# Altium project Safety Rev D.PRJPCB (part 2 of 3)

## Sheet SB_PG6.SCHDOC: (Title)
size B; PageSetup: Record=PageOptions|CenterHorizontal=True|CenterVertical=True|PrintScale=1.09|XCorrection=1.00|YCorrection=1.00|PrintKind=0|BorderSize=5000000|LeftOffset=0|BottomOffset=0|Orientation=2|PaperLength=1000|PaperWidth=1000|Scale=100|PaperSource=7|PrintQuality=-4|MediaType=1|DitherType=10|PaperKind=11x17|PrintScaleMode=1; Engineer: (Engineer); Organization: Institute for Astronomy; Address1: 640 N. Aohoku Place; Address2: Hilo, HI 96720; DocumentNumber: T3-2070; Revision: D; SheetNumber: 6; SheetTotal: 16
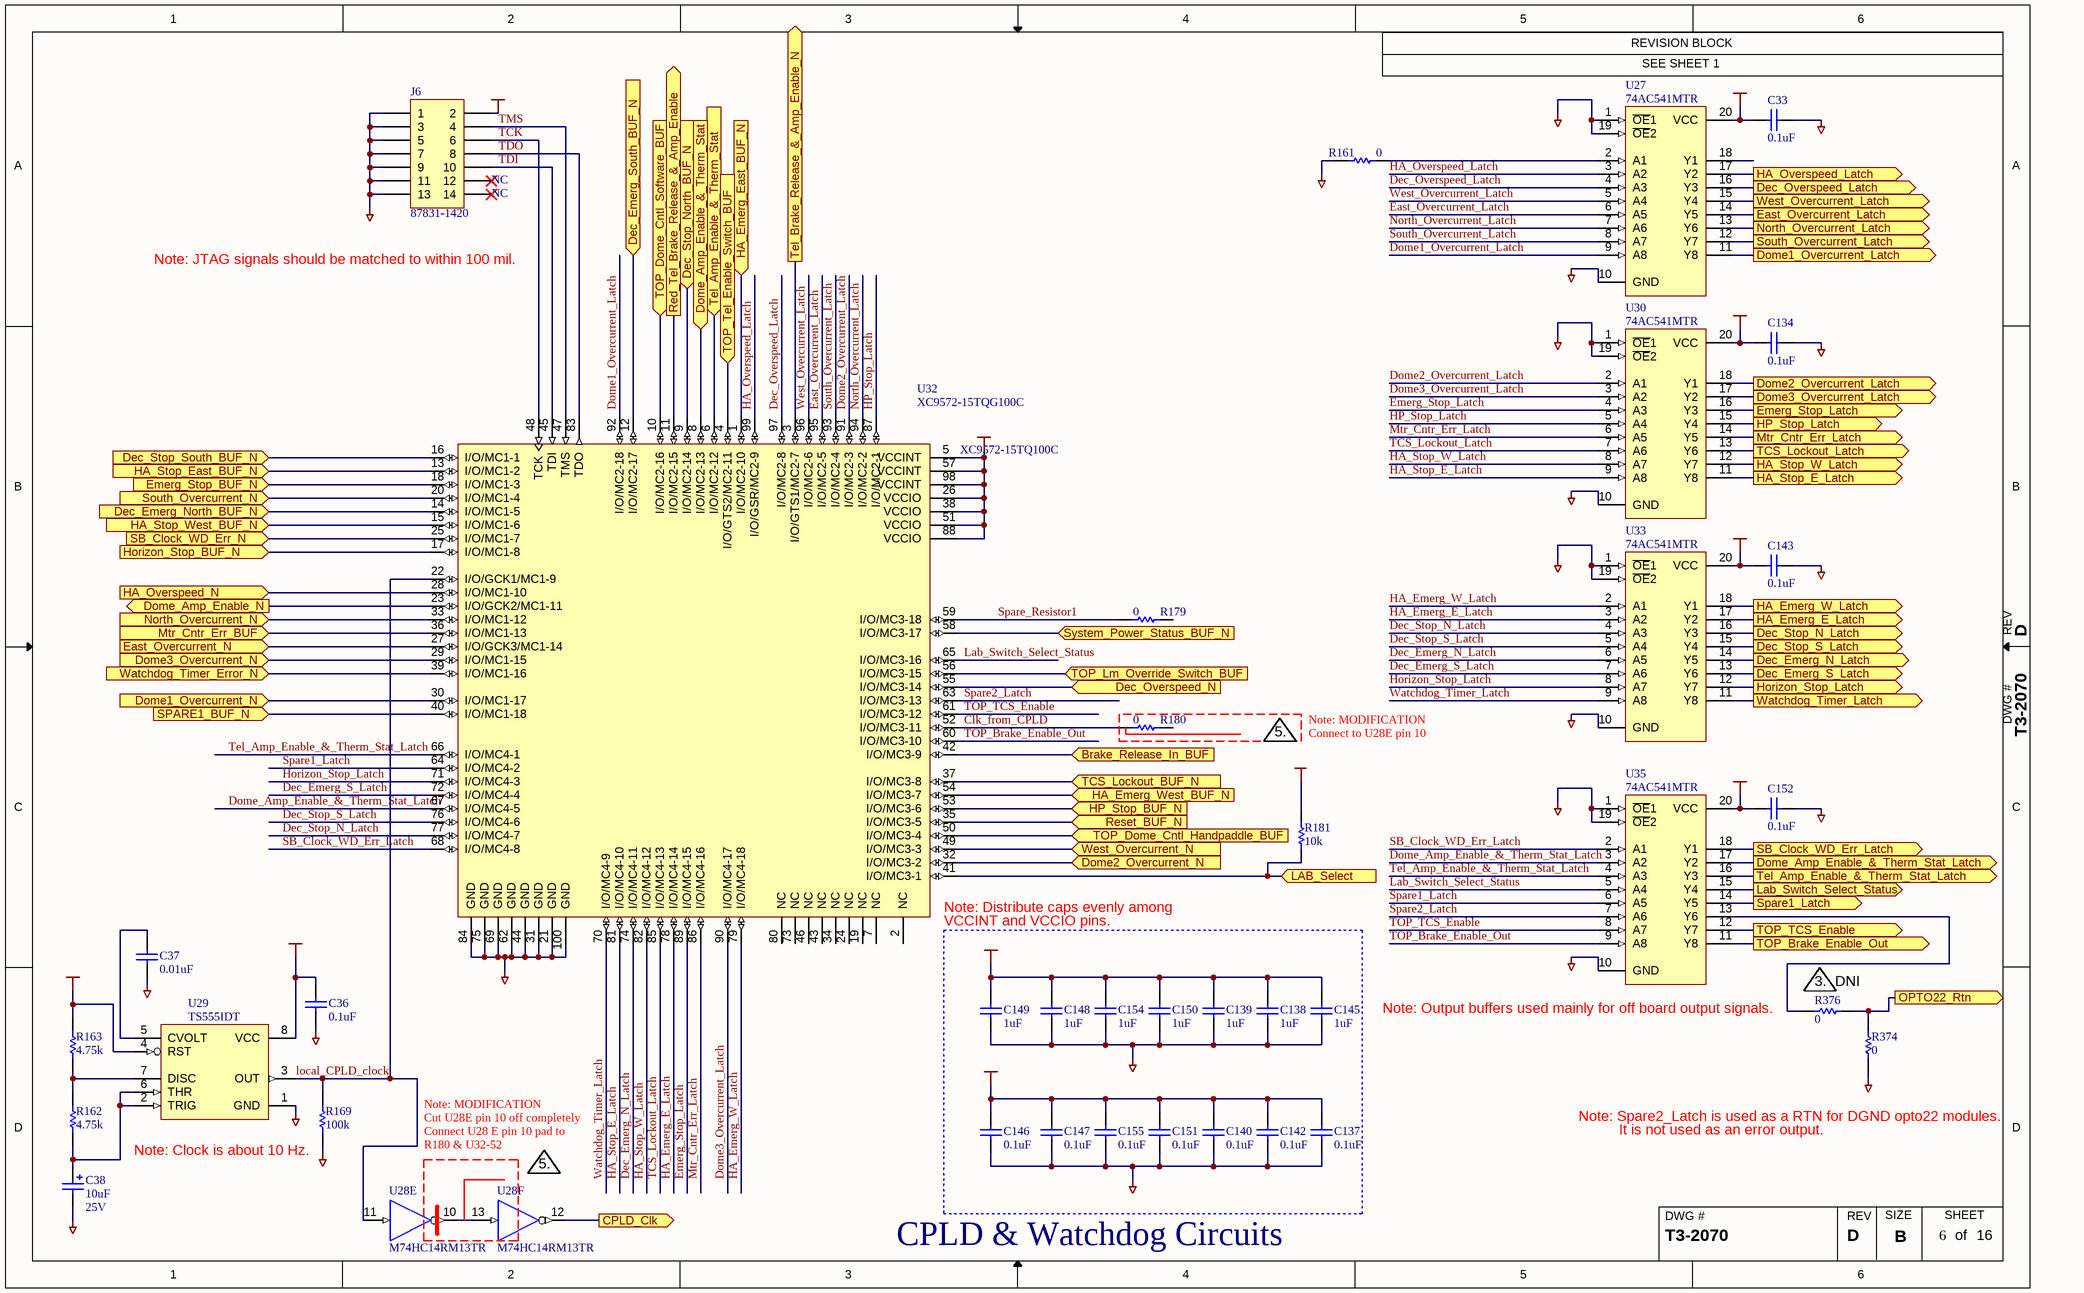
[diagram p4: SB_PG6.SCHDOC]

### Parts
(Parts that share a designator on the sheet are numbered #1, #2 ... from top to bottom, then left to right.)
C33  0.1uF  [1206]
C36  0.1uF  [1206]
C37  0.01uF  [1206]
C38  value 10uF  Voltage: 25V  [CAP_EIA_6032]  (hidden comment: 10uF_25V)
C134  0.1uF  [1206]
C137  0.1uF  [1206]
C138  1uF  [1206]
C139  1uF  [1206]
C140  0.1uF  [1206]
C142  0.1uF  [1206]
C143  0.1uF  [1206]
C145  1uF  [1206]
C146  0.1uF  [1206]
C147  0.1uF  [1206]
C148  1uF  [1206]
C149  1uF  [1206]
C150  1uF  [1206]
C151  0.1uF  [1206]
C152  0.1uF  [1206]
C154  1uF  [1206]
C155  0.1uF  [1206]
Flag?#15  Flag#: 3.  Note: DNI  (graphical)
J6  Part Number: 87831-1420  [HDR_87831-1420]  (hidden comment: Header_14_(7X2)_STR_SHD_col2)
Note?#7  Note#: 5.  (hidden comment: Note_Flag)  (graphical)
Note?#8  Note#: 5.  (hidden comment: Note_Flag)  (graphical)
R161  value 0  [1206]  (hidden comment: 0_jumper)
R162  value 4.75k  [1206]  (hidden comment: 4750)
R163  value 4.75k  [1206]  (hidden comment: 4750)
R169  value 100k  [1206]  (hidden comment: 100000)
R179  value 0  [1206]  (hidden comment: 0_jumper)
R180  value 0  [1206]  (hidden comment: 0_jumper)
R181  value 10k  [1206]  (hidden comment: 10000)
R374  value 0  [1206]  (hidden comment: 0_jumper)
R376  value 0  [1206]  (hidden comment: 0_jumper)  (no BOM)
U27  Part Number: 74AC541MTR  [SOIC_20_WIDE]  (hidden comment: M74HCT541M1R)
U28  M74HC14RM13TR  [SOIC_14_Narrow]  (parts E,F of 6)
U29  TS555IDT  [SOIC_8_NARROW]
U30  Part Number: 74AC541MTR  [SOIC_20_WIDE]  (hidden comment: M74HCT541M1R)
U32  XC9572-15TQ100C  Part Number: XC9572-15TQG100C  [TQ100]
U33  Part Number: 74AC541MTR  [SOIC_20_WIDE]  (hidden comment: M74HCT541M1R)
U35  Part Number: 74AC541MTR  [SOIC_20_WIDE]  (hidden comment: M74HCT541M1R)

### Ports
Brake_Release_In_BUF (in), CPLD_Clk (out), Dec_Emerg_N_Latch (out), Dec_Emerg_North_BUF_N (in), Dec_Emerg_S_Latch (out), Dec_Emerg_South_BUF_N (in), Dec_Overspeed_Latch (out), Dec_Overspeed_N (in), Dec_Stop_N_Latch (out), Dec_Stop_North_BUF_N (in), Dec_Stop_S_Latch (out), Dec_Stop_South_BUF_N (in), Dome1_Overcurrent_Latch (out), Dome1_Overcurrent_N (in), Dome2_Overcurrent_Latch (out), Dome2_Overcurrent_N (in), Dome3_Overcurrent_Latch (out), Dome3_Overcurrent_N (in), Dome_Amp_Enable_&_Therm_Stat (in), Dome_Amp_Enable_&_Therm_Stat_Latch (out), Dome_Amp_Enable_N (out), East_Overcurrent_Latch (out), East_Overcurrent_N (in), Emerg_Stop_BUF_N (in), Emerg_Stop_Latch (out), HA_Emerg_E_Latch (out), HA_Emerg_East_BUF_N (in), HA_Emerg_W_Latch (out), HA_Emerg_West_BUF_N (in), HA_Overspeed_Latch (out), HA_Overspeed_N (in), HA_Stop_E_Latch (out), HA_Stop_East_BUF_N (in), HA_Stop_W_Latch (out), HA_Stop_West_BUF_N (in), Horizon_Stop_BUF_N (in), Horizon_Stop_Latch (out), HP_Stop_BUF_N (in), HP_Stop_Latch (out), LAB_Select (in), Lab_Switch_Select_Status (out), Mtr_Cntr_Err_BUF (in), Mtr_Cntr_Err_Latch (out), North_Overcurrent_Latch (out), North_Overcurrent_N (in), OPTO22_Rtn (out), Red_Tel_Brake_Release_&_Amp_Enable (out), Reset_BUF_N (in), SB_Clock_WD_Err_Latch (out), SB_Clock_WD_Err_N (in), South_Overcurrent_Latch (out), South_Overcurrent_N (in), SPARE1_BUF_N (in), Spare1_Latch (out), System_Power_Status_BUF_N (in), TCS_Lockout_BUF_N (in), TCS_Lockout_Latch (out), Tel_Amp_Enable_&_Therm_Stat (in), Tel_Amp_Enable_&_Therm_Stat_Latch (out), Tel_Brake_Release_&_Amp_Enable_N (out), TOP_Brake_Enable_Out (out), TOP_Dome_Cntl_Handpaddle_BUF (in), TOP_Dome_Cntl_Software_BUF (in), TOP_Lm_Override_Switch_BUF (in), TOP_TCS_Enable (out), TOP_Tel_Enable_Switch_BUF (in), Watchdog_Timer_Error_N (in), Watchdog_Timer_Latch (out), West_Overcurrent_Latch (out), West_Overcurrent_N (in)

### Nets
+5V_DIG: C33.2 C36.2 C134.2 C137.2 C138.2 C139.2 C140.2 C142.2 C143.2 C145.2 C146.2 C147.2 C148.2 C149.2 C150.2 C151.2 C152.2 C154.2 C155.2 J6.2 R163.2 R181.2 U27.20(VCC) U29.4(RST) U29.8(VCC) U30.20(VCC) U32.5(VCCINT) U32.26(VCCIO) U32.38(VCCIO) U32.51(VCCIO) U32.57(VCCINT) U32.88(VCCIO) U32.98(VCCINT) U33.20(VCC) U35.20(VCC)
DGND: C33.1 C36.1 C37.1 C38.2 C134.1 C137.1 C138.1 C139.1 C140.1 C142.1 C143.1 C145.1 C146.1 C147.1 C148.1 C149.1 C150.1 C151.1 C152.1 C154.1 C155.1 J6.1 J6.3 J6.5 J6.7 J6.9 J6.11 J6.13 R161.1 R169.1 R374.1 U27.1(~{OE}1) U27.10(GND) U27.19(~{OE}2) U29.1(GND) U30.1(~{OE}1) U30.10(GND) U30.19(~{OE}2) U32.21(GND) U32.31(GND) U32.44(GND) U32.62(GND) U32.69(GND) U32.75(GND) U32.84(GND) U32.100(GND) U33.1(~{OE}1) U33.10(GND) U33.19(~{OE}2) U35.1(~{OE}1) U35.10(GND) U35.19(~{OE}2)
Brake_Release_In_BUF: U32.42(I/O/MC3-9) ; port Brake_Release_In_BUF
Clk_from_CPLD: R180.1 U32.52(I/O/MC3-11)
CPLD_Clk: U28.12(~{OUT}) ; port CPLD_Clk
Dec Emerg N Latch: U33.14(Y5) ; port Dec_Emerg_N_Latch
Dec Emerg S Latch: U33.13(Y6) ; port Dec_Emerg_S_Latch
Dec OS Latch: U27.16(Y3) ; port Dec_Overspeed_Latch
Dec Stop N Latch: U33.16(Y3) ; port Dec_Stop_N_Latch
Dec Stop S Latch: U33.15(Y4) ; port Dec_Stop_S_Latch
Dec_Emerg_N_Latch: U32.74(I/O/MC4-11) U33.6(A5)
Dec_Emerg_North_BUF_N: U32.14(I/O/MC1-5) ; port Dec_Emerg_North_BUF_N
Dec_Emerg_S_Latch: U32.72(I/O/MC4-4) U33.7(A6)
Dec_Emerg_South_BUF_N: U32.12(I/O/MC2-17) ; port Dec_Emerg_South_BUF_N
Dec_Lab_Select: R181.1 U32.41(I/O/MC3-1) ; port LAB_Select
Dec_Overspeed_Latch: U27.4(A3) U32.97(I/O/MC2-8)
Dec_Overspeed_N: U32.55(I/O/MC3-14) ; port Dec_Overspeed_N
Dec_Stop_N_Latch: U32.77(I/O/MC4-7) U33.4(A3)
Dec_Stop_North_BUF_N: U32.9(I/O/MC2-14) ; port Dec_Stop_North_BUF_N
Dec_Stop_S_Latch: U32.76(I/O/MC4-6) U33.5(A4)
Dec_Stop_South_BUF_N: U32.16(I/O/MC1-1) ; port Dec_Stop_South_BUF_N
Dome1 OC Latch: U27.11(Y8) ; port Dome1_Overcurrent_Latch
Dome1_Overcurrent_Latch: U27.9(A8) U32.92(I/O/MC2-18)
Dome1_Overcurrent_N: U32.30(I/O/MC1-17) ; port Dome1_Overcurrent_N
Dome2 OC Latch: U30.18(Y1) ; port Dome2_Overcurrent_Latch
Dome2_Overcurrent_Latch: U30.2(A1) U32.91(I/O/MC2-3)
Dome2_Overcurrent_N: U32.32(I/O/MC3-2) ; port Dome2_Overcurrent_N
Dome3 OC Latch: U30.17(Y2) ; port Dome3_Overcurrent_Latch
Dome3_Overcurrent_Latch: U30.3(A2) U32.90(I/O/MC4-17)
Dome3_Overcurrent_N: U32.29(I/O/MC1-15) ; port Dome3_Overcurrent_N
Dome Amp Enable & Therm Stat Latch: U35.17(Y2) ; port Dome_Amp_Enable_&_Therm_Stat_Latch
Dome_Amp_Enable_&_Therm_Stat: U32.8(I/O/MC2-13) ; port Dome_Amp_Enable_&_Therm_Stat
Dome_Amp_Enable_&_Therm_Stat_Latch: U32.67(I/O/MC4-5) U35.3(A2)
Dome_Amp_Enable_N: U32.23(I/O/GCK2/MC1-11) ; port Dome_Amp_Enable_N
East OC Latch: U27.14(Y5) ; port East_Overcurrent_Latch
East_Overcurrent_Latch: U27.6(A5) U32.95(I/O/MC2-5)
East_Overcurrent_N: U32.27(I/O/GCK3/MC1-14) ; port East_Overcurrent_N
Emerg Stop Latch: U30.16(Y3) ; port Emerg_Stop_Latch
Emerg_Stop_BUF_N: U32.18(I/O/MC1-3) ; port Emerg_Stop_BUF_N
Emerg_Stop_Latch: U30.4(A3) U32.89(I/O/MC4-15)
HA Emerg E Latch: U33.17(Y2) ; port HA_Emerg_E_Latch
HA Emerg W Latch: U33.18(Y1) ; port HA_Emerg_W_Latch
HA OS Latch: U27.17(Y2) ; port HA_Overspeed_Latch
HA Stop E Latch: U30.11(Y8) ; port HA_Stop_E_Latch
HA Stop W Latch: U30.12(Y7) ; port HA_Stop_W_Latch
HA_Emerg_E_Latch: U32.78(I/O/MC4-14) U33.3(A2)
HA_Emerg_East_BUF_N: U32.1(I/O/MC2-10) ; port HA_Emerg_East_BUF_N
HA_Emerg_W_Latch: U32.79(I/O/MC4-18) U33.2(A1)
HA_Emerg_West_BUF_N: U32.54(I/O/MC3-7) ; port HA_Emerg_West_BUF_N
HA_Overspeed_Latch: U27.3(A2) U32.99(I/O/GSR/MC2-9)
HA_Overspeed_N: U32.28(I/O/MC1-10) ; port HA_Overspeed_N
HA_Stop_E_Latch: U30.9(A8) U32.81(I/O/MC4-10)
HA_Stop_East_BUF_N: U32.13(I/O/MC1-2) ; port HA_Stop_East_BUF_N
HA_Stop_W_Latch: U30.8(A7) U32.82(I/O/MC4-12)
HA_Stop_West_BUF_N: U32.15(I/O/MC1-6) ; port HA_Stop_West_BUF_N
Horizon Stop Latch: U33.12(Y7) ; port Horizon_Stop_Latch
Horizon_Stop_BUF_N: U32.17(I/O/MC1-8) ; port Horizon_Stop_BUF_N
Horizon_Stop_Latch: U32.71(I/O/MC4-3) U33.8(A7)
HP Stop Latch: U30.15(Y4) ; port HP_Stop_Latch
HP_Stop_BUF_N: U32.53(I/O/MC3-6) ; port HP_Stop_BUF_N
HP_Stop_Latch: U30.5(A4) U32.87(I/O/MC2-1)
Lab Switch Select Status: U35.15(Y4) ; port Lab_Switch_Select_Status
Lab_Switch_Select_Status: U32.65(I/O/MC3-16) U35.5(A4)
local_CPLD_clock: R169.2 U28.11(IN) U29.3(OUT) U32.22(I/O/GCK1/MC1-9)
Mtr Cntr Err Latch: U30.14(Y5) ; port Mtr_Cntr_Err_Latch
Mtr_Cntr_Err_BUF: U32.36(I/O/MC1-13) ; port Mtr_Cntr_Err_BUF
Mtr_Cntr_Err_Latch: U30.6(A5) U32.86(I/O/MC4-16)
North OC Latch: U27.13(Y6) ; port North_Overcurrent_Latch
North_Overcurrent_Latch: U27.7(A6) U32.94(I/O/MC2-2)
North_Overcurrent_N: U32.33(I/O/MC1-12) ; port North_Overcurrent_N
Red_Tel_Brake_Release_&_Amp_Enable: U32.11(I/O/MC2-15) ; port Red_Tel_Brake_Release_&_Amp_Enable
Reset_BUF_N: U32.35(I/O/MC3-5) ; port Reset_BUF_N
SB OPTO22 Rtn: R374.2 R376.2 ; port OPTO22_Rtn
SB_Clock_WD_Err_Latch: U35.18(Y1) ; port SB_Clock_WD_Err_Latch
SB_Clock_WD_Err_Latch: U32.68(I/O/MC4-8) U35.2(A1)  [a separate net that carries the same name]
SB_Clock_WD_Err_N: U32.25(I/O/MC1-7) ; port SB_Clock_WD_Err_N
South OS Latch: U27.12(Y7) ; port South_Overcurrent_Latch
South_Overcurrent_Latch: U27.8(A7) U32.93(I/O/MC2-4)
South_Overcurrent_N: U32.20(I/O/MC1-4) ; port South_Overcurrent_N
SPARE1_BUF_N: U32.40(I/O/MC1-18) ; port SPARE1_BUF_N
Spare1_Latch: U32.64(I/O/MC4-2) U35.6(A5)
Spare2_Latch: U32.63(I/O/MC3-13) U35.7(A6)
Spare Latch Out 1: U35.14(Y5) ; port Spare1_Latch
Spare_Resistor1: R179.1 U32.59(I/O/MC3-18)
System_Power_Status_BUF_N: U32.58(I/O/MC3-17) ; port System_Power_Status_BUF_N
TCK: J6.6 U32.48(TCK)
TCS Lockout Latch: U30.13(Y6) ; port TCS_Lockout_Latch
TCS_Lockout_BUF_N: U32.37(I/O/MC3-8) ; port TCS_Lockout_BUF_N
TCS_Lockout_Latch: U30.7(A6) U32.85(I/O/MC4-13)
TDI: J6.10 U32.45(TDI)
TDO: J6.8 U32.83(TDO)
Tel Amp Enable & Therm Stat Latch: U35.16(Y3) ; port Tel_Amp_Enable_&_Therm_Stat_Latch
Tel_Amp_Enable_&_Therm_Stat: U32.6(I/O/MC2-12) ; port Tel_Amp_Enable_&_Therm_Stat
Tel_Amp_Enable_&_Therm_Stat_Latch: U32.66(I/O/MC4-1) U35.4(A3)
Tel_Brake_Release_&_Amp_Enable_N: U32.3(I/O/GTS1/MC2-7) ; port Tel_Brake_Release_&_Amp_Enable_N
TMS: J6.4 U32.47(TMS)
TOP Brake Enable Out: U35.11(Y8) ; port TOP_Brake_Enable_Out
TOP TCS Enable: U35.12(Y7) ; port TOP_TCS_Enable
TOP_Brake_Enable_Out: U32.60(I/O/MC3-10) U35.9(A8)
TOP_Dome_Cntl_Handpaddle_BUF: U32.50(I/O/MC3-4) ; port TOP_Dome_Cntl_Handpaddle_BUF
TOP_Dome_Cntl_Software_BUF: U32.10(I/O/MC2-16) ; port TOP_Dome_Cntl_Software_BUF
TOP_Lm_Override_Switch_BUF: U32.56(I/O/MC3-15) ; port TOP_Lm_Override_Switch_BUF
TOP_TCS_Enable: U32.61(I/O/MC3-12) U35.8(A7)
TOP_Tel_Enable_Switch_BUF: U32.4(I/O/GTS2/MC2-11) ; port TOP_Tel_Enable_Switch_BUF
Watchdog Timer Latch: U33.11(Y8) ; port Watchdog_Timer_Latch
Watchdog_Timer_Error_N: U32.39(I/O/MC1-16) ; port Watchdog_Timer_Error_N
Watchdog_Timer_Latch: U32.70(I/O/MC4-9) U33.9(A8)
West OC Latch: U27.15(Y4) ; port West_Overcurrent_Latch
West_Overcurrent_Latch: U27.5(A4) U32.96(I/O/MC2-6)
West_Overcurrent_N: U32.49(I/O/MC3-3) ; port West_Overcurrent_N
NetC37_2: C37.2 U29.5(CVOLT)
NetC38_1: C38.1 R162.1 U29.2(TRIG) U29.6(THR)
NetR161_2: R161.2 U27.2(A1)
NetR162_2: R162.2 R163.1 U29.7(DISC)
NetR376_1: R376.1 U35.13(Y6)
NetU28_10: U28.10(~{OUT}) U28.13(IN)

Not connected (* = marked no-connect by the designer): J6 12* 14*; R179 2; R180 2; U27 18(Y1); U32 2(NC) 7(NC) 19(NC) 24(NC) 34(NC) 43(NC) 46(NC) 73(NC) 80(NC)

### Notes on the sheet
- (near J6) NC
- Note: JTAG signals should be matched to within 100 mil.
- (near Note?#7) Note: MODIFICATION
- (near Note?#7) Connect to U28E pin 10
- (near U32) Note: Distribute caps evenly among
- (near U32) VCCINT and VCCIO pins.
- (near R376) Note: Output buffers used mainly for off board output signals.
- (near Note?#8) Note: MODIFICATION
- (near R169) Note: Clock is about 10 Hz.
- (near Note?#8) Cut U28E pin 10 off completely
- (near Note?#8) Connect U28 E pin 10 pad to
- (near Note?#8) R180 & U32-52
- (near R374) Note: Spare2_Latch is used as a RTN for DGND opto22 modules.
- It is not used as an error output.
- CPLD & Watchdog Circuits

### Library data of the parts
C33 C36 C134 C137 C140 C142 C143 C146 C147 C151 C152 C155 = 0.1uF: Ceramic Chip Capacitor, 0.1uF, 50V, 10%, X7R; Part Number: C1206C104K5RACTU; Manufacturer: Kemet; BOM_IGNORE: False
C37 = 0.01uF: Ceramic Chip Capacitor, 0.01uF, 50V, 10%, X7R; Part Number: C1206C103K5RACTU; Manufacturer: Kemet; BOM_IGNORE: False
C38 = 10uF_25V: CAP TANTALUM, 10UF, 25V, 10%; Part Number: TAJC106K025R; Manufacturer: AVX
C138 C139 C145 C148-C150 C154 = 1uF: Ceramic Chip Capacitor, 1uF, 50V, 10%, X7R; Part Number: C1206F105K5RACTU; Manufacturer: Kemet; BOM_IGNORE: False
Flag?#15 = Flag
J6 = Header_14_(7X2)_STR_SHD_col2: Header, 14-Pin, Dual row, Straight, Shroud; Manufacturer: Molex/Waldom Electronics Corp.
Note?#7 Note?#8 = Note_Flag: Flag Note; Line1: Physical Modifications:; Line2: Wires, cuts, jumps, etc.; Line3: (line 3)
R161 R179 R180 R374 R376 = 0_jumper: Thick Film Chip Resistor, 0 Ohm, 1206 Size, 0.25 W; Part Number: ERJ-8GEY0R00V; Manufacturer: Panasonic; Tolerance: 1%; Power Rating: 0.25W
R162 R163 = 4750: Thick Film Chip Resistor, 4.75k Ohm, 1% Tolerance, 1206 Size, 0.25 W; Part Number: ERJ-8ENF4751V; Manufacturer: Panasonic; Power Rating: 0.25W
R169 = 100000: Thick Film Chip Resistor, 100k Ohm, 1% Tolerance, 1206 Size, 0.25 W; Part Number: ERJ-8ENF1003V; Manufacturer: Panasonic; Power Rating: 0.25W
R181 = 10000: Thick Film Chip Resistor, 10k Ohm, 1% Tolerance, 1206 Size, 0.25 W; Part Number: ERJ-8ENF1002V; Manufacturer: Panasonic; Power Rating: 0.25W
U27 U30 U33 U35 = M74HCT541M1R: Octal Bus Buffer with 3 State Outputs (Non Inverted); Manufacturer: STMicroelectronics
U28 = M74HC14RM13TR: Hex Schmitt-Trigger Inverter; Manufacturer: STMicroelectronics
U29 = TS555IDT: IC PRECISION TIMER , CMOS, 8-SOIC; Manufacturer: STMicroelectronics
U32 = XC9572-15TQ100C: XC9500 CPLD with 72 Macrocells, 100-Pin TQFP, Commercial Grade; Manufacturer: Xilinx

## Sheet SB_PG3.SCHDOC: (Title)
size B; PageSetup: Record=PageOptions|CenterHorizontal=True|CenterVertical=True|PrintScale=1.09|XCorrection=1.00|YCorrection=1.00|PrintKind=0|BorderSize=5000000|LeftOffset=0|BottomOffset=0|Orientation=2|PaperLength=1000|PaperWidth=1000|Scale=100|PaperSource=7|PrintQuality=-4|MediaType=1|DitherType=10|PaperKind=11x17|PrintScaleMode=1; Engineer: (Engineer); Organization: Institute for Astronomy; Address1: 640 N. Aohoku Place; Address2: Hilo, HI 96720; DocumentNumber: T3-2070; Revision: D; SheetNumber: 3; SheetTotal: 16
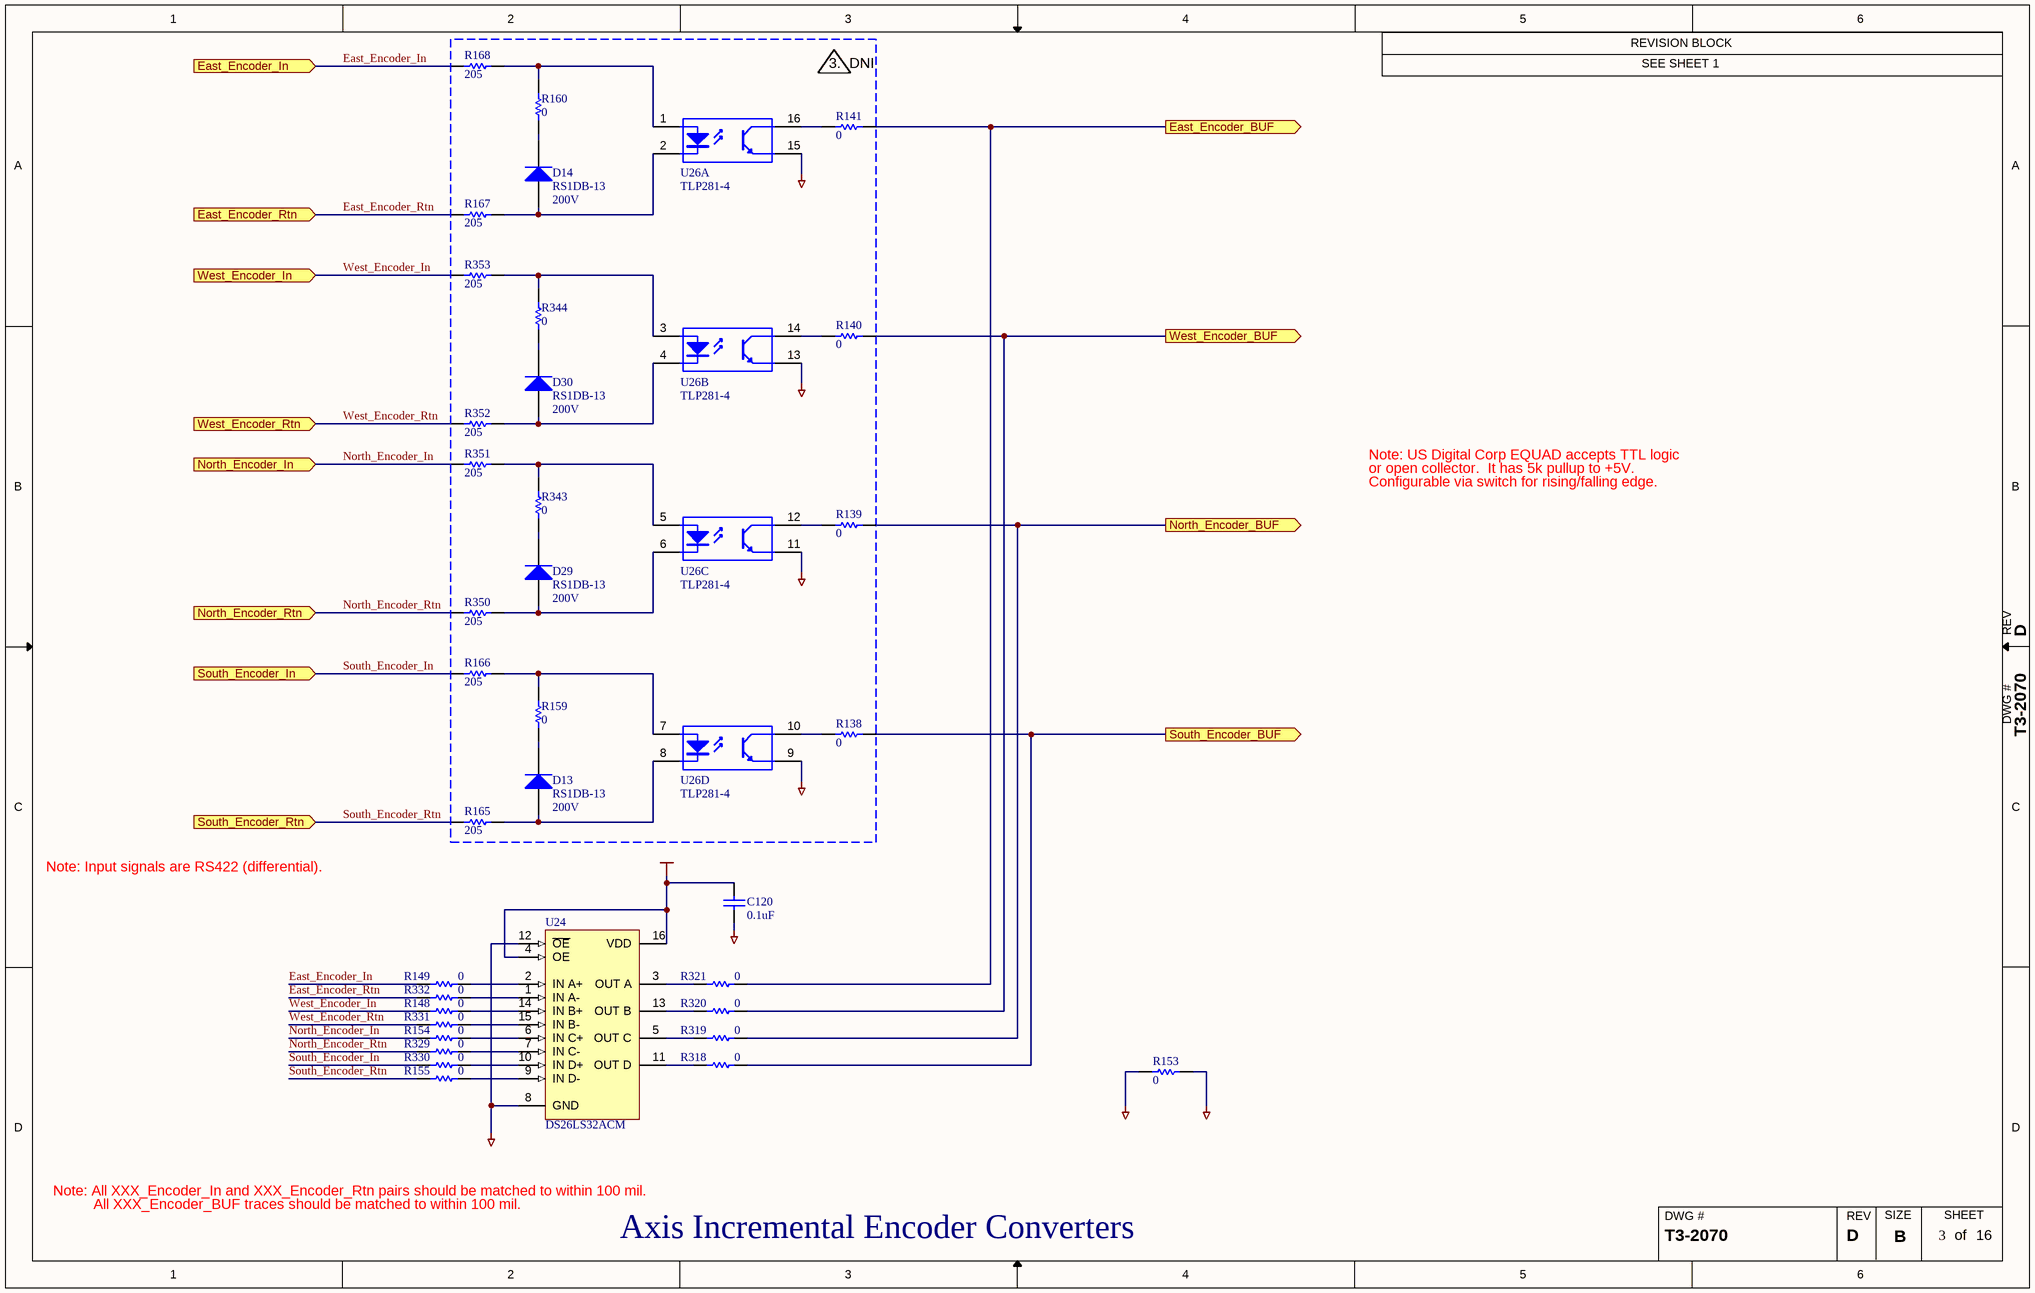
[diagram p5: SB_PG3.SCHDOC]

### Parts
(Parts that share a designator on the sheet are numbered #1, #2 ... from top to bottom, then left to right.)
C120  0.1uF  [1206]
D13  Voltage: 200V  [DO-214AA (SMB) & MARKING]  (hidden comment: RS1DB-13)  (no BOM)
D14  Voltage: 200V  [DO-214AA (SMB) & MARKING]  (hidden comment: RS1DB-13)  (no BOM)
D29  Voltage: 200V  [DO-214AA (SMB) & MARKING]  (hidden comment: RS1DB-13)  (no BOM)
D30  Voltage: 200V  [DO-214AA (SMB) & MARKING]  (hidden comment: RS1DB-13)  (no BOM)
Flag?#16  Flag#: 3.  Note: DNI  (graphical)
R138  value 0  [1206]  (hidden comment: 0_jumper)  (no BOM)
R139  value 0  [1206]  (hidden comment: 0_jumper)  (no BOM)
R140  value 0  [1206]  (hidden comment: 0_jumper)  (no BOM)
R141  value 0  [1206]  (hidden comment: 0_jumper)  (no BOM)
R148  value 0  [1206]  (hidden comment: 0_jumper)
R149  value 0  [1206]  (hidden comment: 0_jumper)
R153  value 0  [1206]  (hidden comment: 0_jumper)
R154  value 0  [1206]  (hidden comment: 0_jumper)
R155  value 0  [1206]  (hidden comment: 0_jumper)
R159  value 0  [1206]  (hidden comment: 0_jumper)  (no BOM)
R160  value 0  [1206]  (hidden comment: 0_jumper)  (no BOM)
R165  205  [1206]  (no BOM)
R166  205  [1206]  (no BOM)
R167  205  [1206]  (no BOM)
R168  205  [1206]  (no BOM)
R318  value 0  [1206]  (hidden comment: 0_jumper)
R319  value 0  [1206]  (hidden comment: 0_jumper)
R320  value 0  [1206]  (hidden comment: 0_jumper)
R321  value 0  [1206]  (hidden comment: 0_jumper)
R329  value 0  [1206]  (hidden comment: 0_jumper)
R330  value 0  [1206]  (hidden comment: 0_jumper)
R331  value 0  [1206]  (hidden comment: 0_jumper)
R332  value 0  [1206]  (hidden comment: 0_jumper)
R343  value 0  [1206]  (hidden comment: 0_jumper)  (no BOM)
R344  value 0  [1206]  (hidden comment: 0_jumper)  (no BOM)
R350  205  [1206]  (no BOM)
R351  205  [1206]  (no BOM)
R352  205  [1206]  (no BOM)
R353  205  [1206]  (no BOM)
U24  DS26LS32ACM  [SOIC_16_NARROW]
U26  TLP281-4  [SOIC_16_C5.85]  (parts A,B,C,D of 4)  (no BOM)

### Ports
East_Encoder_BUF (out), East_Encoder_In (in), East_Encoder_Rtn (in), North_Encoder_BUF (out), North_Encoder_In (in), North_Encoder_Rtn (in), South_Encoder_BUF (out), South_Encoder_In (in), South_Encoder_Rtn (in), West_Encoder_BUF (out), West_Encoder_In (in), West_Encoder_Rtn (in)

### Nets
+5V_DIG: C120.2 U24.4(OE) U24.16(VDD)
DGND: C120.1 R153.1 U24.8(GND) U24.12(~{OE}) U26.9(E) U26.11(E) U26.13(E) U26.15(E)
EGND: R153.2
East_Encoder_BUF: R141.1 R321.2 ; port East_Encoder_BUF
East_Encoder_In: R149.1 R168.1 ; port East_Encoder_In
East_Encoder_Rtn: R167.1 R332.1 ; port East_Encoder_Rtn
North_Encoder_BUF: R139.1 R319.2 ; port North_Encoder_BUF
North_Encoder_In: R154.1 R351.1 ; port North_Encoder_In
North_Encoder_Rtn: R329.1 R350.1 ; port North_Encoder_Rtn
South_Encoder_BUF: R138.1 R318.2 ; port South_Encoder_BUF
South_Encoder_In: R166.1 R330.1 ; port South_Encoder_In
South_Encoder_Rtn: R155.1 R165.1 ; port South_Encoder_Rtn
West_Encoder_BUF: R140.1 R320.2 ; port West_Encoder_BUF
West_Encoder_In: R148.1 R353.1 ; port West_Encoder_In
West_Encoder_Rtn: R331.1 R352.1 ; port West_Encoder_Rtn
NetD13_A: D13.A R165.2 U26.8(K)
NetD13_K: D13.K R159.1
NetD14_A: D14.A R167.2 U26.2(K)
NetD14_K: D14.K R160.1
NetD29_A: D29.A R350.2 U26.6(K)
NetD29_K: D29.K R343.1
NetD30_A: D30.A R352.2 U26.4(K)
NetD30_K: D30.K R344.1
NetR138_2: R138.2 U26.10(C)
NetR139_2: R139.2 U26.12(C)
NetR140_2: R140.2 U26.14(C)
NetR141_2: R141.2 U26.16(C)
NetR148_2: R148.2 U24.14(IN_B+)
NetR149_2: R149.2 U24.2(IN_A+)
NetR154_2: R154.2 U24.6(IN_C+)
NetR155_2: R155.2 U24.9(IN_D-)
NetR159_2: R159.2 R166.2 U26.7(A)
NetR160_2: R160.2 R168.2 U26.1(A)
NetR318_1: R318.1 U24.11(OUT_D)
NetR319_1: R319.1 U24.5(OUT_C)
NetR320_1: R320.1 U24.13(OUT_B)
NetR321_1: R321.1 U24.3(OUT_A)
NetR329_2: R329.2 U24.7(IN_C-)
NetR330_2: R330.2 U24.10(IN_D+)
NetR331_2: R331.2 U24.15(IN_B-)
NetR332_2: R332.2 U24.1(IN_A-)
NetR343_2: R343.2 R351.2 U26.5(A)
NetR344_2: R344.2 R353.2 U26.3(A)

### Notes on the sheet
- Note: US Digital Corp EQUAD accepts TTL logic
- or open collector.  It has 5k pullup to +5V.
- Configurable via switch for rising/falling edge.
- Note: Input signals are RS422 (differential).
- Note: All XXX_Encoder_In and XXX_Encoder_Rtn pairs should be matched to within 100 mil.
- All XXX_Encoder_BUF traces should be matched to within 100 mil.
- Axis Incremental Encoder Converters

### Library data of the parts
C120 = 0.1uF: as C33 on sheet SB_PG6
D13 D14 D29 D30 = RS1DB-13: RECT FAST RECOVERY 200V 1A; Manufacturer: Diodes Inc
Flag?#16 = Flag
R138-R141 R148 R149 R153-R155 R159 R160 R318-R321 R329-R332 R343 R344 = 0_jumper: as R161 on sheet SB_PG6
R165-R168 R350-R353 = 205: Thick Film Chip Resistor, 205 Ohm, 1% Tolerance, 1206 Size, 0.25 W; Part Number: ERJ-8ENF2050V; Manufacturer: Panasonic; Power Rating: 0.25W; BOM_IGNORE: False
U24 = DS26LS32ACM: IC LINE RCVR QUAD DIFF; Manufacturer: National Semiconductor
U26 = TLP281-4: Photocoupler; Manufacturer: Toshiba

## Sheet SB_PG2.SCHDOC: (Title)
size B; Engineer: (Engineer); Organization: Institute for Astronomy; Address1: 640 N. Aohoku Place; Address2: Hilo, HI 96720; DocumentNumber: T3-2070; Revision: D; SheetNumber: 2; SheetTotal: 16
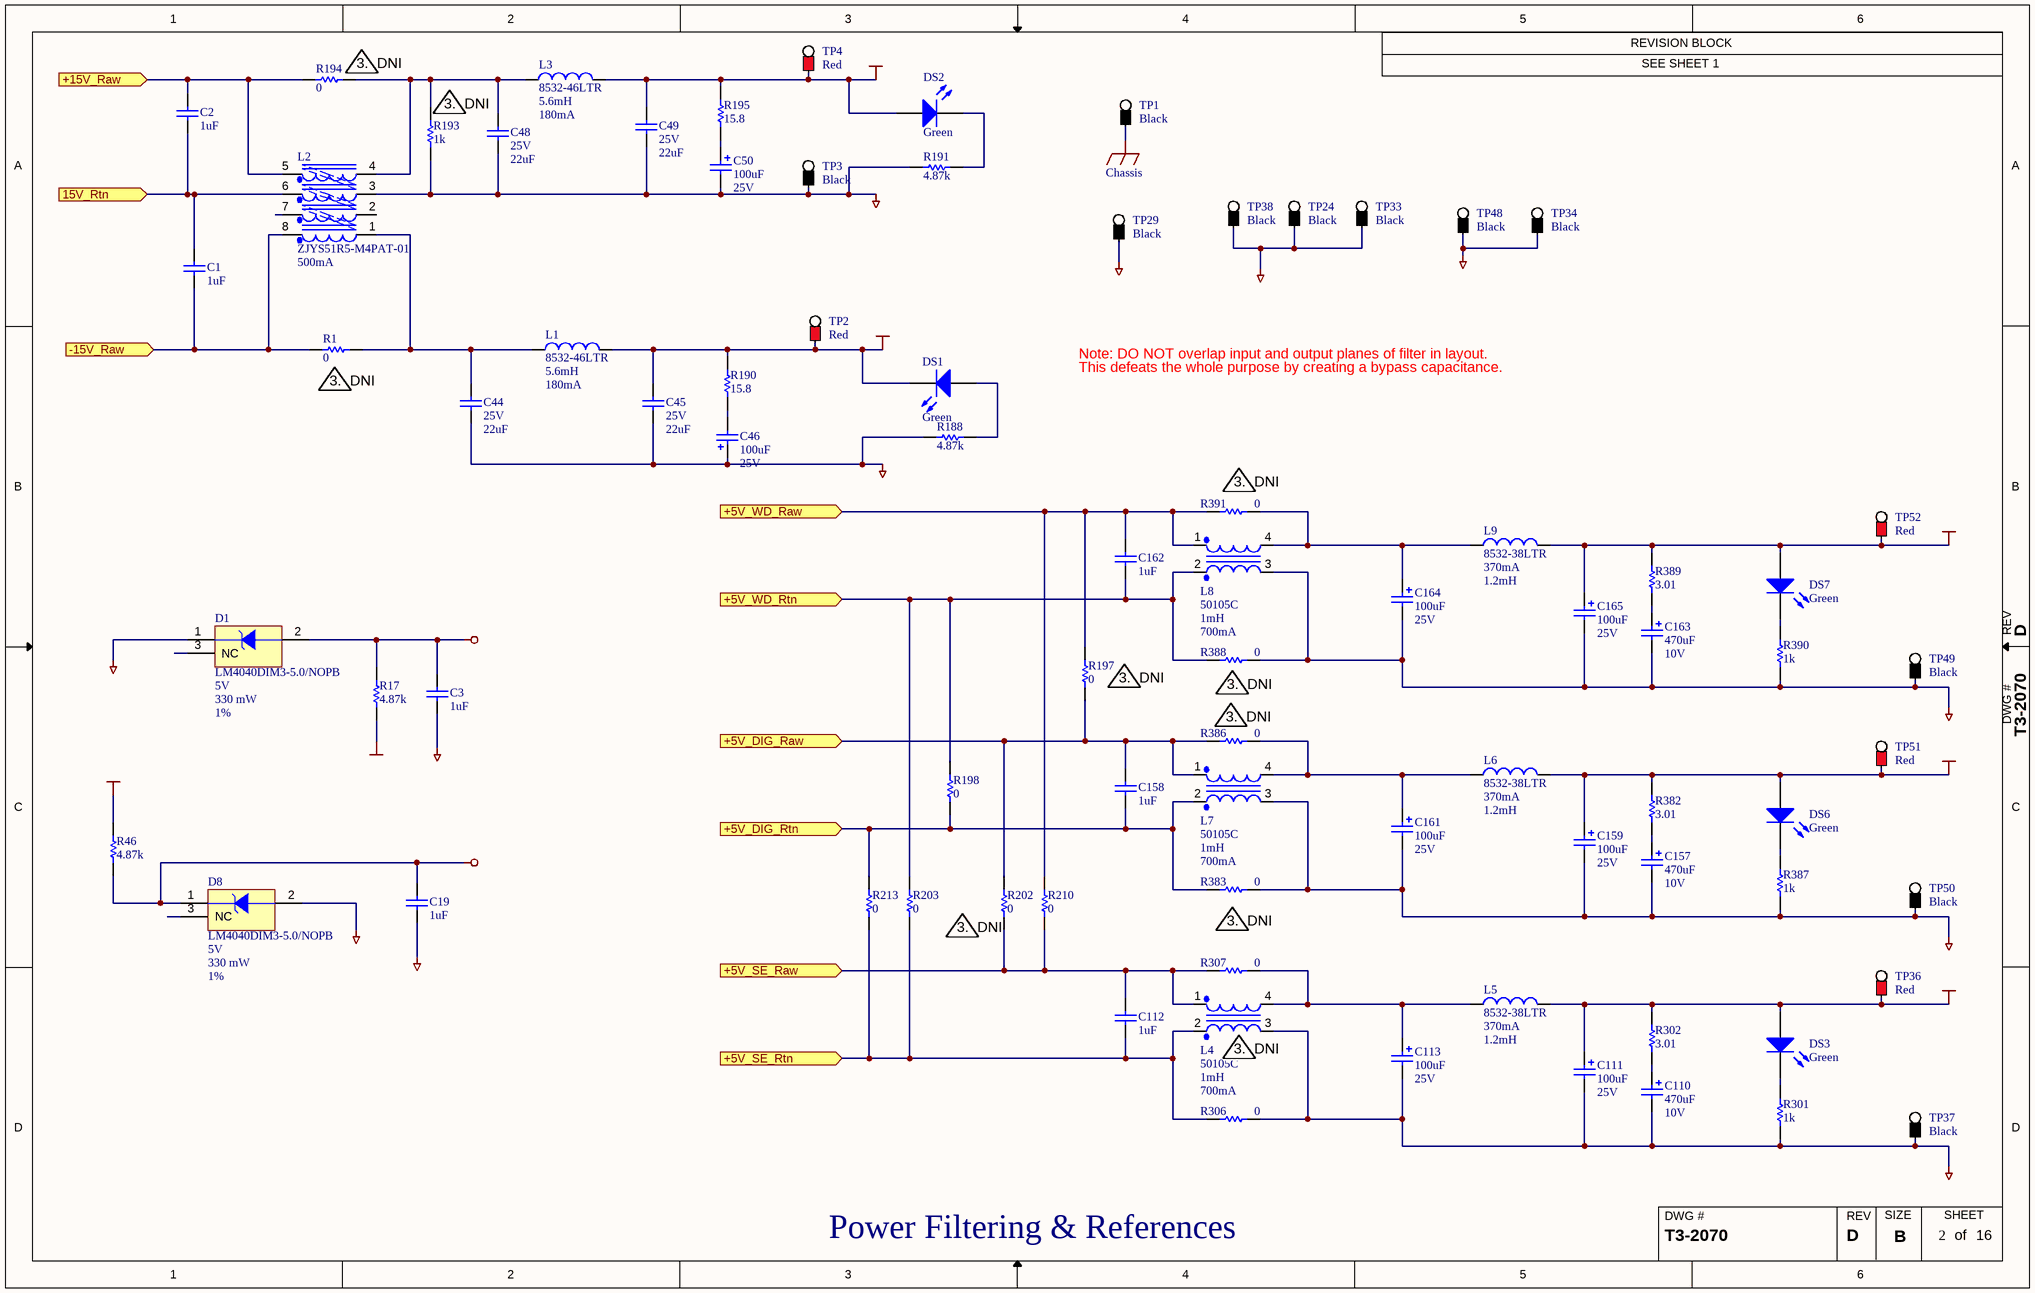
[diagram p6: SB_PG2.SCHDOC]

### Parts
(Parts that share a designator on the sheet are numbered #1, #2 ... from top to bottom, then left to right.)
C1  1uF  [1206]
C2  1uF  [1206]
C3  1uF  [1206]
C19  1uF  [1206]
C44  value 22uF  Voltage Rating: 25V  [1210]  (hidden comment: 22uF_15V)
C45  value 22uF  Voltage Rating: 25V  [1210]  (hidden comment: 22uF_15V)
C46  value 100uF  Voltage: 25V  [CAP_EIA_7343]  (hidden comment: 100uF_25V)
C48  value 22uF  Voltage Rating: 25V  [1210]  (hidden comment: 22uF_15V)
C49  value 22uF  Voltage Rating: 25V  [1210]  (hidden comment: 22uF_15V)
C50  value 100uF  Voltage: 25V  [CAP_EIA_7343]  (hidden comment: 100uF_25V)
C110  value 470uF  Voltage: 10V  [CAP_EIA_7343]  (hidden comment: 470uF_10V)
C111  value 100uF  Voltage: 25V  [CAP_EIA_7343]  (hidden comment: 100uF_25V)
C112  1uF  [1206]
C113  value 100uF  Voltage: 25V  [CAP_EIA_7343]  (hidden comment: 100uF_25V)
C157  value 470uF  Voltage: 10V  [CAP_EIA_7343]  (hidden comment: 470uF_10V)
C158  1uF  [1206]
C159  value 100uF  Voltage: 25V  [CAP_EIA_7343]  (hidden comment: 100uF_25V)
C161  value 100uF  Voltage: 25V  [CAP_EIA_7343]  (hidden comment: 100uF_25V)
C162  1uF  [1206]
C163  value 470uF  Voltage: 10V  [CAP_EIA_7343]  (hidden comment: 470uF_10V)
C164  value 100uF  Voltage: 25V  [CAP_EIA_7343]  (hidden comment: 100uF_25V)
C165  value 100uF  Voltage: 25V  [CAP_EIA_7343]  (hidden comment: 100uF_25V)
D1  LM4040DIM3-5.0/NOPB  value 5V  Power: 330 mW  Tolerance: 1%  [SOT23]
D8  LM4040DIM3-5.0/NOPB  value 5V  Power: 330 mW  Tolerance: 1%  [SOT23]
DS1  value Green  [LED_1210]  (hidden comment: LTST-C930KGKT)
DS2  value Green  [LED_1210]  (hidden comment: LTST-C930KGKT)
DS3  value Green  [LED_1210]  (hidden comment: LTST-C930KGKT)
DS6  value Green  [LED_1210]  (hidden comment: LTST-C930KGKT)
DS7  value Green  [LED_1210]  (hidden comment: LTST-C930KGKT)
Flag?#17  Flag#: 3.  Note: DNI  (graphical)
Flag?#18  Flag#: 3.  Note: DNI  (graphical)
Flag?#19  Flag#: 3.  Note: DNI  (graphical)
Flag?#20  Flag#: 3.  Note: DNI  (graphical)
Flag?#21  Flag#: 3.  Note: DNI  (graphical)
Flag?#22  Flag#: 3.  Note: DNI  (graphical)
Flag?#23  Flag#: 3.  Note: DNI  (graphical)
Flag?#24  Flag#: 3.  Note: DNI  (graphical)
Flag?#25  Flag#: 3.  Note: DNI  (graphical)
Flag?#26  Flag#: 3.  Note: DNI  (graphical)
L1  value 5.6mH  Current: 180mA  [8532_inductor]  (hidden comment: 8532-46LTR)
L2  Current: 500mA  [ZJYS51R5-M4PA_INDCUTOR]  (hidden comment: ZJYS51R5-M4PAT-01)
L3  value 5.6mH  Current: 180mA  [8532_inductor]  (hidden comment: 8532-46LTR)
L4  value 1mH  Current: 700mA  [5000_inductor]  (hidden comment: 50105C)  (no BOM)
L5  value 1.2mH  Current: 370mA  [8532_inductor]  (hidden comment: 8532-38LTR)
L6  value 1.2mH  Current: 370mA  [8532_inductor]  (hidden comment: 8532-38LTR)
L7  value 1mH  Current: 700mA  [5000_inductor]  (hidden comment: 50105C)
L8  value 1mH  Current: 700mA  [5000_inductor]  (hidden comment: 50105C)
L9  value 1.2mH  Current: 370mA  [8532_inductor]  (hidden comment: 8532-38LTR)
R1  value 0  [1206]  (hidden comment: 0_jumper)  (no BOM)
R17  value 4.87k  [1206]  (hidden comment: 4870)
R46  value 4.87k  [1206]  (hidden comment: 4870)
R188  value 4.87k  [1206]  (hidden comment: 4870)
R190  15.8  [1206]
R191  value 4.87k  [1206]  (hidden comment: 4870)
R193  value 1k  [1206]  (hidden comment: 1000)  (no BOM)
R194  value 0  [1206]  (hidden comment: 0_jumper)  (no BOM)
R195  15.8  [1206]
R197  value 0  [1206]  (hidden comment: 0_jumper)  (no BOM)
R198  value 0  [1206]  (hidden comment: 0_jumper)
R202  value 0  [1206]  (hidden comment: 0_jumper)  (no BOM)
R203  value 0  [1206]  (hidden comment: 0_jumper)
R210  value 0  [1206]  (hidden comment: 0_jumper)
R213  value 0  [1206]  (hidden comment: 0_jumper)
R301  value 1k  [1206]  (hidden comment: 1000)
R302  3.01  [1206]
R306  value 0  [1206]  (hidden comment: 0_jumper)
R307  value 0  [1206]  (hidden comment: 0_jumper)
R382  3.01  [1206]
R383  value 0  [1206]  (hidden comment: 0_jumper)  (no BOM)
R386  value 0  [1206]  (hidden comment: 0_jumper)  (no BOM)
R387  value 1k  [1206]  (hidden comment: 1000)
R388  value 0  [1206]  (hidden comment: 0_jumper)  (no BOM)
R389  3.01  [1206]
R390  value 1k  [1206]  (hidden comment: 1000)
R391  value 0  [1206]  (hidden comment: 0_jumper)  (no BOM)
TP1  value Black  [TP_COMPACT]  (hidden comment: TP_5006)
TP2  value Red  [TP_COMPACT]  (hidden comment: TP_5005)
TP3  value Black  [TP_COMPACT]  (hidden comment: TP_5006)
TP4  value Red  [TP_COMPACT]  (hidden comment: TP_5005)
TP24  value Black  [TP_COMPACT]  (hidden comment: TP_5006)
TP29  value Black  [TP_COMPACT]  (hidden comment: TP_5006)
TP33  value Black  [TP_COMPACT]  (hidden comment: TP_5006)
TP34  value Black  [TP_COMPACT]  (hidden comment: TP_5006)
TP36  value Red  [TP_COMPACT]  (hidden comment: TP_5005)
TP37  value Black  [TP_COMPACT]  (hidden comment: TP_5006)
TP38  value Black  [TP_COMPACT]  (hidden comment: TP_5006)
TP48  value Black  [TP_COMPACT]  (hidden comment: TP_5006)
TP49  value Black  [TP_COMPACT]  (hidden comment: TP_5006)
TP50  value Black  [TP_COMPACT]  (hidden comment: TP_5006)
TP51  value Red  [TP_COMPACT]  (hidden comment: TP_5005)
TP52  value Red  [TP_COMPACT]  (hidden comment: TP_5005)

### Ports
15V_Rtn (in), +5V_DIG_Raw (in), +5V_DIG_Rtn (in), +5V_SE_Raw (in), +5V_SE_Rtn (in), +5V_WD_Raw (in), +5V_WD_Rtn (in), +15V_Raw (in), -15V_Raw (in)

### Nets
+5_VREF: C19.2 D8.1(V+) R46.1
+5V_DIG: C159.1 DS6.A L6.2 R382.2 TP51.1
+5V_SE: C111.1 DS3.A L5.2 R302.2 TP36.1
+5V_WD: C165.1 DS7.A L9.2 R389.2 TP52.1
+15V: C49.2 DS2.A L3.2 R46.2 R195.2 TP4.1
-5_VREF: C3.2 D1.2(V-) R17.2
-15V: C45.2 DS1.K L1.2 R17.1 R190.2 TP2.1
AGND: C3.1 C19.1 C44.1 C45.1 C46.1 C48.1 C49.1 C50.2 D1.1(V+) D8.2(V-) L2.3 R188.1 R191.1 R193.1 TP3.1 TP24.1 TP33.1 TP38.1
CHASSIS: TP1.1
DGND: C157.2 C159.2 C161.2 L7.3 R383.2 R387.1 TP34.1 TP48.1 TP50.1
PCGND: TP29.1
SEGND: C110.2 C111.2 C113.2 L4.3 R301.1 R306.2 TP37.1
WDGND: C163.2 C164.2 C165.2 L8.3 R388.2 R390.1 TP49.1
15V_Rtn: C1.2 C2.1 L2.6 ; port 15V_Rtn
+5V_DIG_Raw: C158.2 L7.1 R197.1 R202.2 R386.1 ; port +5V_DIG_Raw
+5V_DIG_Rtn: C158.1 L7.2 R198.1 R213.2 R383.1 ; port +5V_DIG_Rtn
+5V_SE_Raw: C112.2 L4.1 R202.1 R210.1 R307.1 ; port +5V_SE_Raw
+5V_SE_Rtn: C112.1 L4.2 R203.1 R213.1 R306.1 ; port +5V_SE_Rtn
+5V_WD_Raw: C162.2 L8.1 R197.2 R210.2 R391.1 ; port +5V_WD_Raw
+5V_WD_Rtn: C162.1 L8.2 R198.2 R203.2 R388.1 ; port +5V_WD_Rtn
+15V_Raw: C2.2 L2.5 R194.1 ; port +15V_Raw
-15V_Raw: C1.1 L2.8 R1.1 ; port -15V_Raw
NetC44_2: C44.2 L1.1 L2.1 R1.2
NetC46_2: C46.2 R190.1
NetC48_2: C48.2 L2.4 L3.1 R193.2 R194.2
NetC50_1: C50.1 R195.1
NetC110_1: C110.1 R302.1
NetC113_1: C113.1 L4.4 L5.1 R307.2
NetC157_1: C157.1 R382.1
NetC161_1: C161.1 L6.1 L7.4 R386.2
NetC163_1: C163.1 R389.1
NetC164_1: C164.1 L8.4 L9.1 R391.2
NetDS1_A: DS1.A R188.2
NetDS2_K: DS2.K R191.2
NetDS3_K: DS3.K R301.2
NetDS6_K: DS6.K R387.2
NetDS7_K: DS7.K R390.2

Not connected (* = marked no-connect by the designer): D1 3(NC); D8 3(NC); L2 2 7

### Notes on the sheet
- Chassis
- Note: DO NOT overlap input and output planes of filter in layout.
- This defeats the whole purpose by creating a bypass capacitance.
- Power Filtering & References

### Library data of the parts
C1-C3 C19 C112 C158 C162 = 1uF: as C138 on sheet SB_PG6
C44 C45 C48 C49 = 22uF_15V: Ceramic Chip Capacitor, 22uF, 25V, 20%, X5R; Part Number: ECJ-4YB1E226M; Manufacturer: Panasonic; BOM_IGNORE: False
C46 C50 C111 C113 C159 C161 C164 C165 = 100uF_25V: CAP TANTALUM, 100UF, 25V, 10%; Part Number: T495X107K025ZTE150; Manufacturer: Kemet
C110 C157 C163 = 470uF_10V: CAP TANTALUM 470UF 10V 10%; Part Number: B45197A2477K509; Manufacturer: Kemet
D1 D8 = LM4040DIM3-5.0/NOPB: 5V Shunt Voltage Reference, 1%; Manufacturer: National Semiconductor
DS1-DS3 DS6 DS7 = LTST-C930KGKT: LED, Green, Dome, 1210 SMD; Manufacturer: Lite-On Inc; BOM_IGNORE: FALSE
Flag?#17-Flag?#26 = Flag
L1 L3 = 8532-46LTR: Inductor, 5.6mH, 180mA, 15%; Manufacturer: API Delevan Inc
L2 = ZJYS51R5-M4PAT-01: Inductor, CM, 4 terminal, 500mA; Manufacturer: TDK
L4 L7 L8 = 50105C: Inductor, CM, 1mH, 700mA, 50%; Manufacturer: muRata; Coupling Factor: 0.999
L5 L6 L9 = 8532-38LTR: Inductor, 1.2mH, 370mA, 15%; Manufacturer: API Delevan Inc
R1 R194 R197 R198 R202 R203 R210 R213 R306 R307 R383 R386 R388 R391 = 0_jumper: as R161 on sheet SB_PG6
R17 R46 R188 R191 = 4870: Thick Film Chip Resistor, 4.87k Ohm, 1% Tolerance, 1206 Size, 0.25 W; Part Number: ERJ-8ENF4871V; Manufacturer: Panasonic; Power Rating: 0.25W
R190 R195 = 15.8: Thick Film Chip Resistor, 15.8 Ohm, 1% Tolerance, 1206 Size, 0.25 W; Part Number: ERJ-8ENF15R8V; Manufacturer: Panasonic; Power Rating: 0.25W
R193 R301 R387 R390 = 1000: Thick Film Chip Resistor, 1k Ohm, 1% Tolerance, 1206 Size, 0.25 W; Part Number: ERJ-8ENF1001V; Manufacturer: Panasonic; Power Rating: 0.25W
R302 R382 R389 = 3.01: Thick Film Chip Resistor, 3.01 Ohm, 1% Tolerance, 1206 Size, 0.25W; Part Number: RC1206FR-073R01L; Manufacturer: Yageo
TP1 TP3 TP24 TP29 TP33 TP34 TP37 TP38 TP48-TP50 = TP_5006: Black, Compact Test Point, Thru Hole, Loop; Part Number: 5006; Manufacturer: Keystone; BOM_IGNORE: FALSE
TP2 TP4 TP36 TP51 TP52 = TP_5005: Red, Compact Test Point, Thru Hole, Loop; Part Number: 5005; Manufacturer: Keystone; BOM_IGNORE: FALSE

## Sheet SB_PG11.SCHDOC: (Title)
size B; PageSetup: Record=PageOptions|CenterHorizontal=True|CenterVertical=True|PrintScale=1.09|XCorrection=1.00|YCorrection=1.00|PrintKind=0|BorderSize=5000000|LeftOffset=0|BottomOffset=0|Orientation=2|PaperLength=1000|PaperWidth=1000|Scale=100|PaperSource=7|PrintQuality=-4|MediaType=1|DitherType=10|PaperKind=11x17|PrintScaleMode=1; Engineer: (Engineer); Organization: Institute for Astronomy; Address1: 640 N. Aohoku Place; Address2: Hilo, HI 96720; DocumentNumber: T3-2070; Revision: D; SheetNumber: 11; SheetTotal: 16
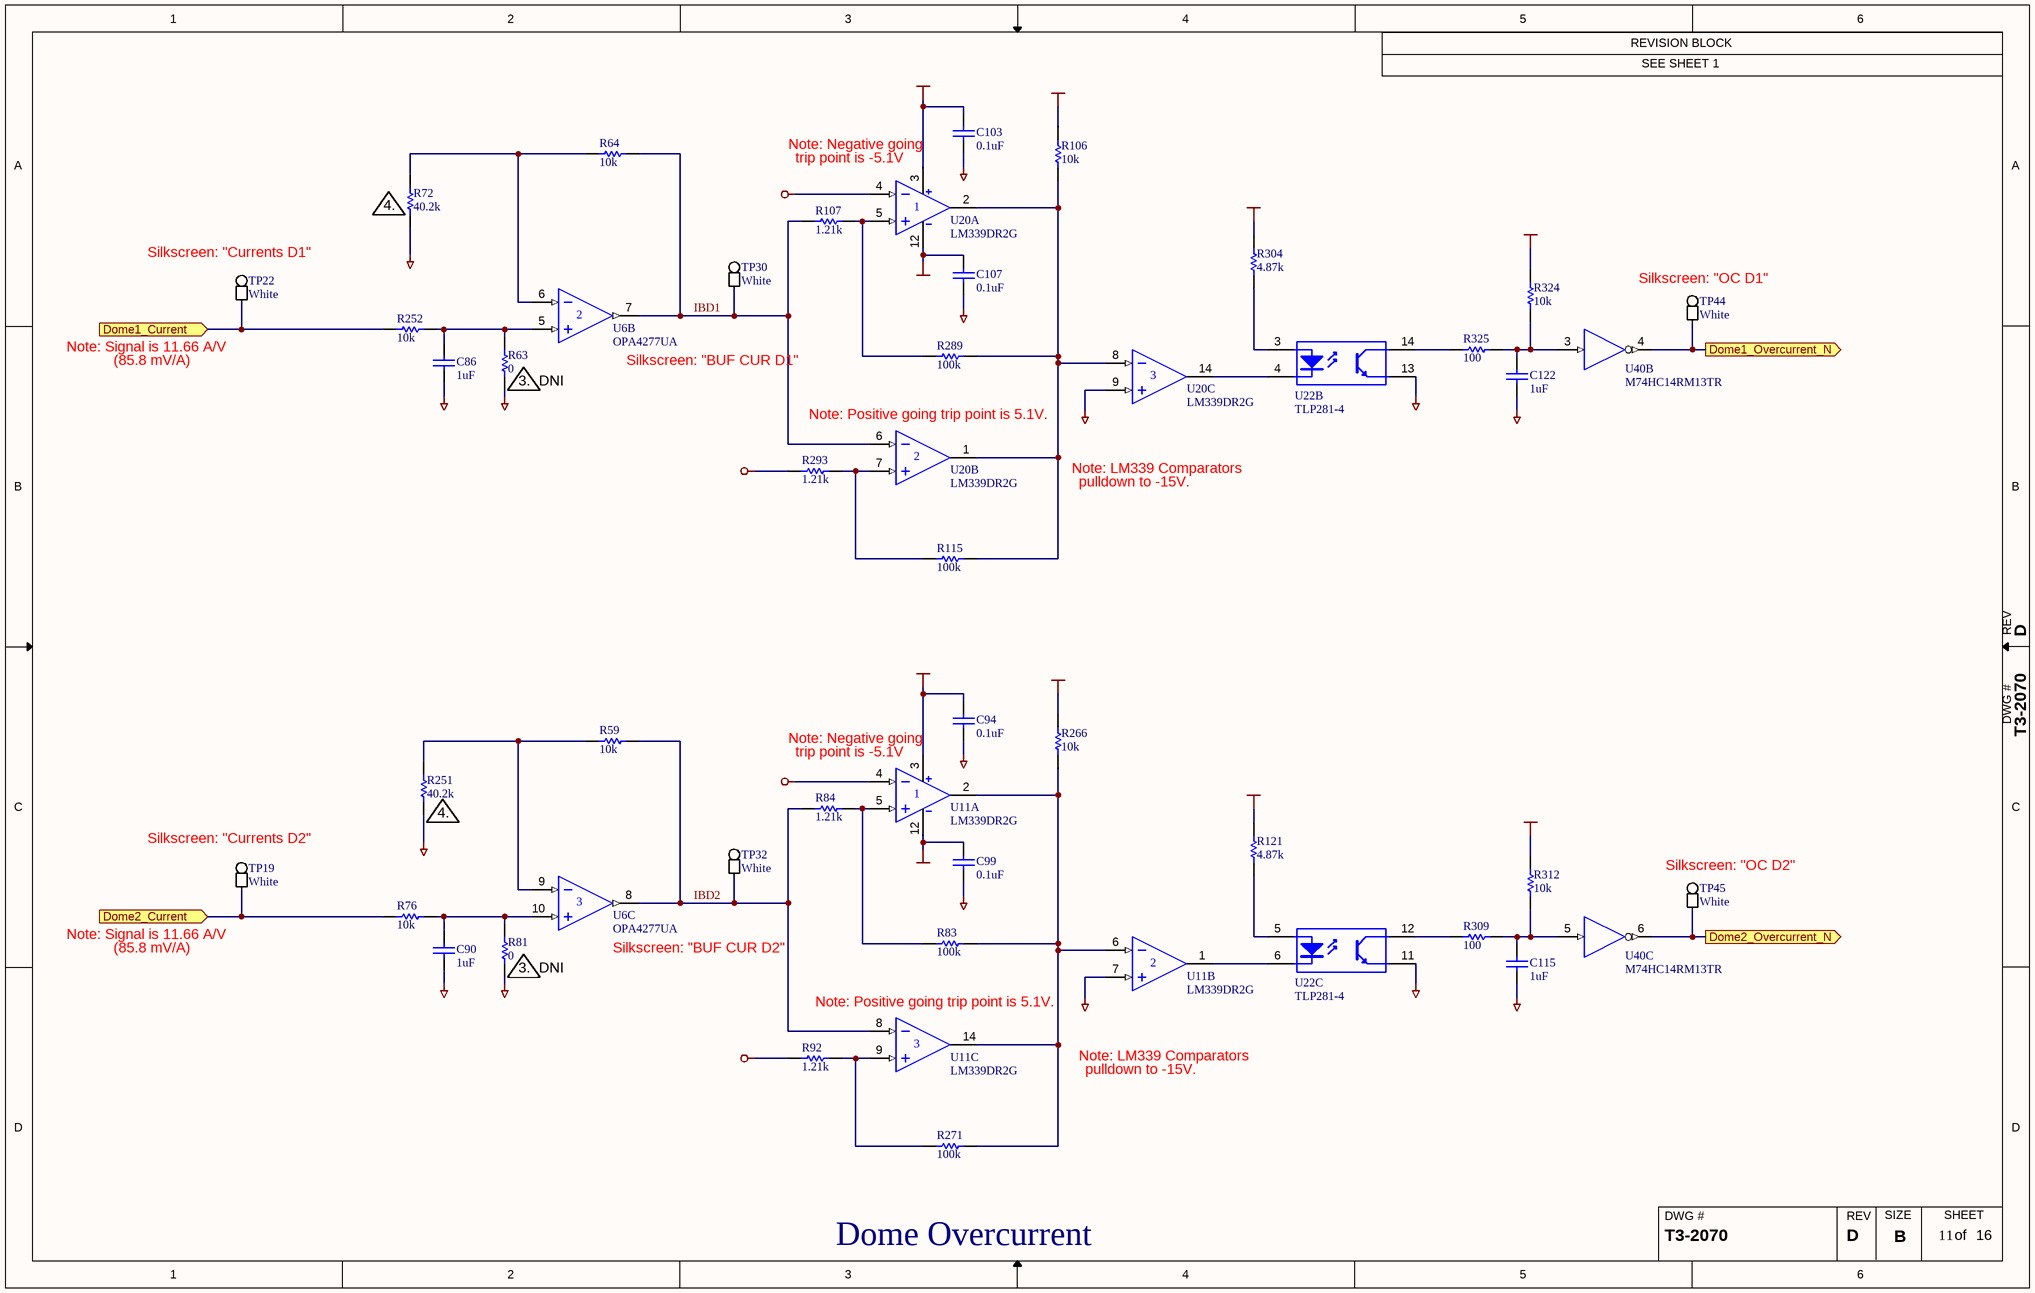
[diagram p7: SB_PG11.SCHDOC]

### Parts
(Parts that share a designator on the sheet are numbered #1, #2 ... from top to bottom, then left to right.)
C86  1uF  [1206]
C90  1uF  [1206]
C94  0.1uF  [1206]
C99  0.1uF  [1206]
C103  0.1uF  [1206]
C107  0.1uF  [1206]
C115  1uF  [1206]
C122  1uF  [1206]
Flag?#27  Flag#: 4.  (hidden comment: Flag)  (graphical)
Flag?#28  Flag#: 3.  Note: DNI  (graphical)
Flag?#29  Flag#: 4.  (hidden comment: Flag)  (graphical)
Flag?#30  Flag#: 3.  Note: DNI  (graphical)
R59  value 10k  [1206]  (hidden comment: 10000)
R63  value 0  [1206]  (hidden comment: 0_jumper)  (no BOM)
R64  value 10k  [1206]  (hidden comment: 10000)
R72  value 40.2k  [1206]  (hidden comment: 40200)
R76  value 10k  [1206]  (hidden comment: 10000)
R81  value 0  [1206]  (hidden comment: 0_jumper)  (no BOM)
R83  value 100k  [1206]  (hidden comment: 100000)
R84  value 1.21k  [1206]  (hidden comment: 1210)
R92  value 1.21k  [1206]  (hidden comment: 1210)
R106  value 10k  [1206]  (hidden comment: 10000)
R107  value 1.21k  [1206]  (hidden comment: 1210)
R115  value 100k  [1206]  (hidden comment: 100000)
R121  value 4.87k  [1206]  (hidden comment: 4870)
R251  value 40.2k  [1206]  (hidden comment: 40200)
R252  value 10k  [1206]  (hidden comment: 10000)
R266  value 10k  [1206]  (hidden comment: 10000)
R271  value 100k  [1206]  (hidden comment: 100000)
R289  value 100k  [1206]  (hidden comment: 100000)
R293  value 1.21k  [1206]  (hidden comment: 1210)
R304  value 4.87k  [1206]  (hidden comment: 4870)
R309  100  [1206]
R312  value 10k  [1206]  (hidden comment: 10000)
R324  value 10k  [1206]  (hidden comment: 10000)
R325  100  [1206]
TP19  value White  [TP_COMPACT]  (hidden comment: TP_5007)
TP22  value White  [TP_COMPACT]  (hidden comment: TP_5007)
TP30  value White  [TP_COMPACT]  (hidden comment: TP_5007)
TP32  value White  [TP_COMPACT]  (hidden comment: TP_5007)
TP44  value White  [TP_COMPACT]  (hidden comment: TP_5007)
TP45  value White  [TP_COMPACT]  (hidden comment: TP_5007)
U6  OPA4277UA  [SOIC_14_Narrow]  (parts B,C of 4)
U11  LM339DR2G  [SOIC_14_Narrow]  (parts A,B,C of 4)
U20  LM339DR2G  [SOIC_14_Narrow]  (parts A,B,C of 4)
U22  TLP281-4  [SOIC_16_C5.85]  (parts B,C of 4)
U40  M74HC14RM13TR  [SOIC_14_Narrow]  (parts B,C of 6)

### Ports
Dome1_Current (in), Dome1_Overcurrent_N (out), Dome2_Current (in), Dome2_Overcurrent_N (out)

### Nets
+5_VREF: R92.1 R293.1
+5V_DIG: R312.2 R324.2
+15V: C94.2 C103.2 R106.2 R121.2 R266.2 R304.2 U11.3(V+) U20.3(V+)
-5_VREF: U11.4(IN-) U20.4(IN-)
-15V: C99.2 C107.2 U11.12(V-) U20.12(V-)
AGND: C86.1 C90.1 C94.1 C99.1 C103.1 C107.1 R63.1 R72.1 R81.1 R251.1 U11.7(IN+) U20.9(IN+)
DGND: C115.1 C122.1 U22.11(E) U22.13(E)
Dome1 Current: R252.1 TP22.1 ; port Dome1_Current
Dome1_Overcurrent_N: TP44.1 U40.4(~{OUT}) ; port Dome1_Overcurrent_N
Dome2 Current: R76.1 TP19.1 ; port Dome2_Current
Dome2_Overcurrent_N: TP45.1 U40.6(~{OUT}) ; port Dome2_Overcurrent_N
IBD1: R64.2 R107.1 TP30.1 U6.7(OUT) U20.6(IN-)
IBD2: R59.2 R84.1 TP32.1 U6.8(OUT) U11.8(IN-)
NetC86_2: C86.2 R63.2 R252.2 U6.5(IN+)
NetC90_2: C90.2 R76.2 R81.2 U6.10(IN+)
NetC115_2: C115.2 R309.1 R312.1 U40.5(IN)
NetC122_2: C122.2 R324.1 R325.1 U40.3(IN)
NetR59_1: R59.1 R251.2 U6.9(IN-)
NetR64_1: R64.1 R72.2 U6.6(IN-)
NetR83_1: R83.1 R84.2 U11.5(IN+)
NetR83_2: R83.2 R266.1 R271.2 U11.2(OUT) U11.6(IN-) U11.14(OUT)
NetR92_2: R92.2 R271.1 U11.9(IN+)
NetR106_1: R106.1 R115.2 R289.2 U20.1(OUT) U20.2(OUT) U20.8(IN-)
NetR107_2: R107.2 R289.1 U20.5(IN+)
NetR115_1: R115.1 R293.2 U20.7(IN+)
NetR121_1: R121.1 U22.5(A)
NetR304_1: R304.1 U22.3(A)
NetR309_2: R309.2 U22.12(C)
NetR325_2: R325.2 U22.14(C)
NetU11_1: U11.1(OUT) U22.6(K)
NetU20_14: U20.14(OUT) U22.4(K)

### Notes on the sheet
- Note: Negative going
- trip point is -5.1V
- (near TP22) Silkscreen: "Currents D1"
- (near TP44) Silkscreen: "OC D1"
- (near TP22) Note: Signal is 11.66 A/V
- (85.8 mV/A)
- (near U6) Silkscreen: "BUF CUR D1"
- (near U20) Note: Positive going trip point is 5.1V.
- Note: LM339 Comparators
- pulldown to -15V.
- (near U11) trip point is -5.1V
- (near TP19) Silkscreen: "Currents D2"
- (near TP45) Silkscreen: "OC D2"
- (near TP19) Note: Signal is 11.66 A/V
- (near U6) Silkscreen: "BUF CUR D2"
- (near U11) Note: Positive going trip point is 5.1V.
- Dome Overcurrent

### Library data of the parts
C86 C90 C115 C122 = 1uF: as C138 on sheet SB_PG6
C94 C99 C103 C107 = 0.1uF: as C33 on sheet SB_PG6
Flag?#28 Flag?#30 = Flag
R59 R64 R76 R106 R252 R266 R312 R324 = 10000: as R181 on sheet SB_PG6
R63 R81 = 0_jumper: as R161 on sheet SB_PG6
R72 R251 = 40200: Thick Film Chip Resistor, 40.2k Ohm, 1% Tolerance, 1206 Size, 0.25 W; Part Number: ERJ-8ENF4022V; Manufacturer: Panasonic; Power Rating: 0.25W
R83 R115 R271 R289 = 100000: as R169 on sheet SB_PG6
R84 R92 R107 R293 = 1210: Thick Film Chip Resistor, 1.21k Ohm, 1% Tolerance, 1206 Size, 0.25 W; Part Number: ERJ-8ENF1211V; Manufacturer: Panasonic; Power Rating: 0.25W
R121 R304 = 4870: as R17 on sheet SB_PG2
R309 R325 = 100: Thick Film Chip Resistor, 100 Ohm, 1% Tolerance, 1206 Size, 0.25 W; Part Number: ERJ-8ENF1000V; Manufacturer: Panasonic; Power Rating: 0.25W
TP19 TP22 TP30 TP32 TP44 TP45 = TP_5007: White, Compact Test Point, Thru Hole, Loop; Part Number: 5007; Manufacturer: Keystone; BOM_IGNORE: FALSE
U6 = OPA4277UA: QUAD PRECISION OPAMP 14-SOIC; Manufacturer: Texas Instruments
U11 U20 = LM339DR2G: Quad Comparator; Manufacturer: ON Semiconductor
U22 = TLP281-4: Photocoupler; Manufacturer: Toshiba
U40 = M74HC14RM13TR: as U28 on sheet SB_PG6

## Sheet SB_PG12.SCHDOC: (Title)
size B; PageSetup: Record=PageOptions|CenterHorizontal=True|CenterVertical=True|PrintScale=1.09|XCorrection=1.00|YCorrection=1.00|PrintKind=0|BorderSize=5000000|LeftOffset=0|BottomOffset=0|Orientation=2|PaperLength=1000|PaperWidth=1000|Scale=100|PaperSource=7|PrintQuality=-4|MediaType=1|DitherType=10|PaperKind=11x17|PrintScaleMode=1; Engineer: (Engineer); Organization: Institute for Astronomy; Address1: 640 N. Aohoku Place; Address2: Hilo, HI 96720; DocumentNumber: T3-2070; Revision: D; SheetNumber: 12; SheetTotal: 16
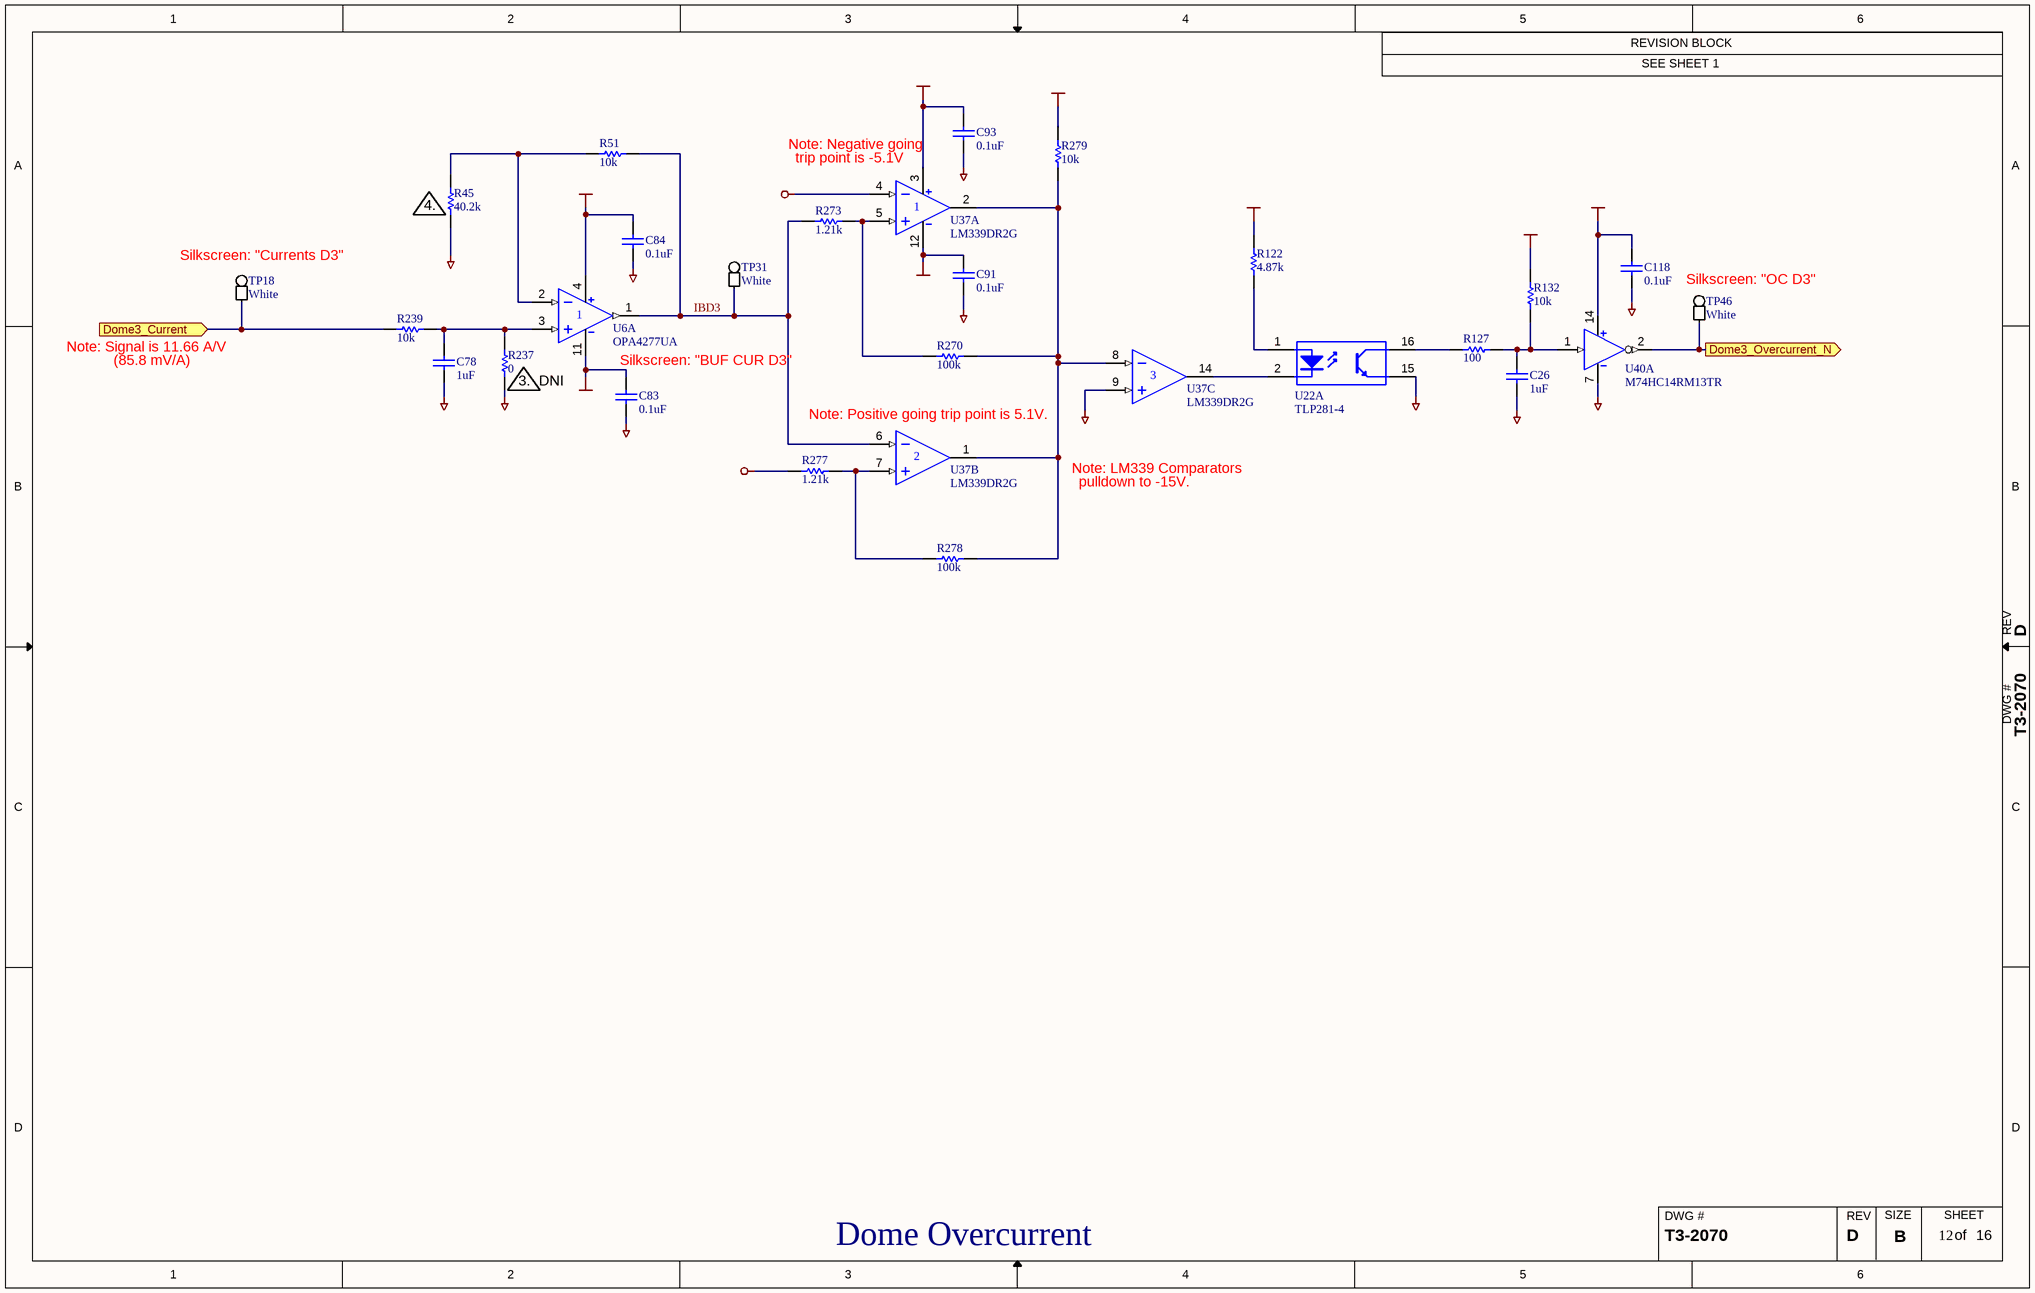
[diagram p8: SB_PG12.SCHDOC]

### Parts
(Parts that share a designator on the sheet are numbered #1, #2 ... from top to bottom, then left to right.)
C26  1uF  [1206]
C78  1uF  [1206]
C83  0.1uF  [1206]
C84  0.1uF  [1206]
C91  0.1uF  [1206]
C93  0.1uF  [1206]
C118  0.1uF  [1206]
Flag?#31  Flag#: 4.  (hidden comment: Flag)  (graphical)
Flag?#32  Flag#: 3.  Note: DNI  (graphical)
R45  value 40.2k  [1206]  (hidden comment: 40200)
R51  value 10k  [1206]  (hidden comment: 10000)
R122  value 4.87k  [1206]  (hidden comment: 4870)
R127  100  [1206]
R132  value 10k  [1206]  (hidden comment: 10000)
R237  value 0  [1206]  (hidden comment: 0_jumper)  (no BOM)
R239  value 10k  [1206]  (hidden comment: 10000)
R270  value 100k  [1206]  (hidden comment: 100000)
R273  value 1.21k  [1206]  (hidden comment: 1210)
R277  value 1.21k  [1206]  (hidden comment: 1210)
R278  value 100k  [1206]  (hidden comment: 100000)
R279  value 10k  [1206]  (hidden comment: 10000)
TP18  value White  [TP_COMPACT]  (hidden comment: TP_5007)
TP31  value White  [TP_COMPACT]  (hidden comment: TP_5007)
TP46  value White  [TP_COMPACT]  (hidden comment: TP_5007)
U6  OPA4277UA  [SOIC_14_Narrow]  (part A of 4)
U22  TLP281-4  [SOIC_16_C5.85]  (part A of 4)
U37  LM339DR2G  [SOIC_14_Narrow]  (parts A,B,C of 4)
U40  M74HC14RM13TR  [SOIC_14_Narrow]  (part A of 6)

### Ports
Dome3_Current (in), Dome3_Overcurrent_N (out)

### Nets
+5_VREF: R277.1
+5V_DIG: C118.2 R132.2 U40.14(VDD)
+15V: C84.2 C93.2 R122.2 R279.2 U6.4(V+) U37.3(V+)
-5_VREF: U37.4(IN-)
-15V: C83.2 C91.2 U6.11(V-) U37.12(V-)
AGND: C78.1 C83.1 C84.1 C91.1 C93.1 R45.1 R237.1 U37.9(IN+)
DGND: C26.1 C118.1 U22.15(E) U40.7(GND)
Dome3 Current: R239.1 TP18.1 ; port Dome3_Current
Dome3_Overcurrent_N: TP46.1 U40.2(~{OUT}) ; port Dome3_Overcurrent_N
IBD3: R51.2 R273.1 TP31.1 U6.1(OUT) U37.6(IN-)
NetC26_2: C26.2 R127.1 R132.1 U40.1(IN)
NetC78_2: C78.2 R237.2 R239.2 U6.3(IN+)
NetR45_2: R45.2 R51.1 U6.2(IN-)
NetR122_1: R122.1 U22.1(A)
NetR127_2: R127.2 U22.16(C)
NetR270_1: R270.1 R273.2 U37.5(IN+)
NetR270_2: R270.2 R278.2 R279.1 U37.1(OUT) U37.2(OUT) U37.8(IN-)
NetR277_2: R277.2 R278.1 U37.7(IN+)
NetU22_2: U22.2(K) U37.14(OUT)

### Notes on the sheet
- Note: Negative going
- trip point is -5.1V
- (near TP18) Silkscreen: "Currents D3"
- (near TP46) Silkscreen: "OC D3"
- (near TP18) Note: Signal is 11.66 A/V
- (85.8 mV/A)
- Silkscreen: "BUF CUR D3"
- (near U37) Note: Positive going trip point is 5.1V.
- Note: LM339 Comparators
- pulldown to -15V.
- Dome Overcurrent

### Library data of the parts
C26 C78 = 1uF: as C138 on sheet SB_PG6
C83 C84 C91 C93 C118 = 0.1uF: as C33 on sheet SB_PG6
Flag?#32 = Flag
R45 = 40200: as R72 on sheet SB_PG11
R51 R132 R239 R279 = 10000: as R181 on sheet SB_PG6
R122 = 4870: as R17 on sheet SB_PG2
R127 = 100: as R309 on sheet SB_PG11
R237 = 0_jumper: as R161 on sheet SB_PG6
R270 R278 = 100000: as R169 on sheet SB_PG6
R273 R277 = 1210: as R84 on sheet SB_PG11
TP18 TP31 TP46 = TP_5007: as TP19 on sheet SB_PG11
U6 = OPA4277UA: as U6 on sheet SB_PG11
U22 = TLP281-4: Photocoupler; Manufacturer: Toshiba
U37 = LM339DR2G: as U11 on sheet SB_PG11
U40 = M74HC14RM13TR: as U28 on sheet SB_PG6

## Sheet SB_PG14.SCHDOC: (Title)
size B; PageSetup: Record=PageOptions|CenterHorizontal=True|CenterVertical=True|PrintScale=1.09|XCorrection=1.00|YCorrection=1.00|PrintKind=0|BorderSize=5000000|LeftOffset=0|BottomOffset=0|Orientation=2|PaperLength=1000|PaperWidth=1000|Scale=100|PaperSource=7|PrintQuality=-4|MediaType=1|DitherType=10|PaperKind=11x17|PrintScaleMode=1; Engineer: (Engineer); Organization: Institute for Astronomy; Address1: 640 N. Aohoku Place; Address2: Hilo, HI 96720; DocumentNumber: T3-2070; Revision: D; SheetNumber: 14; SheetTotal: 16
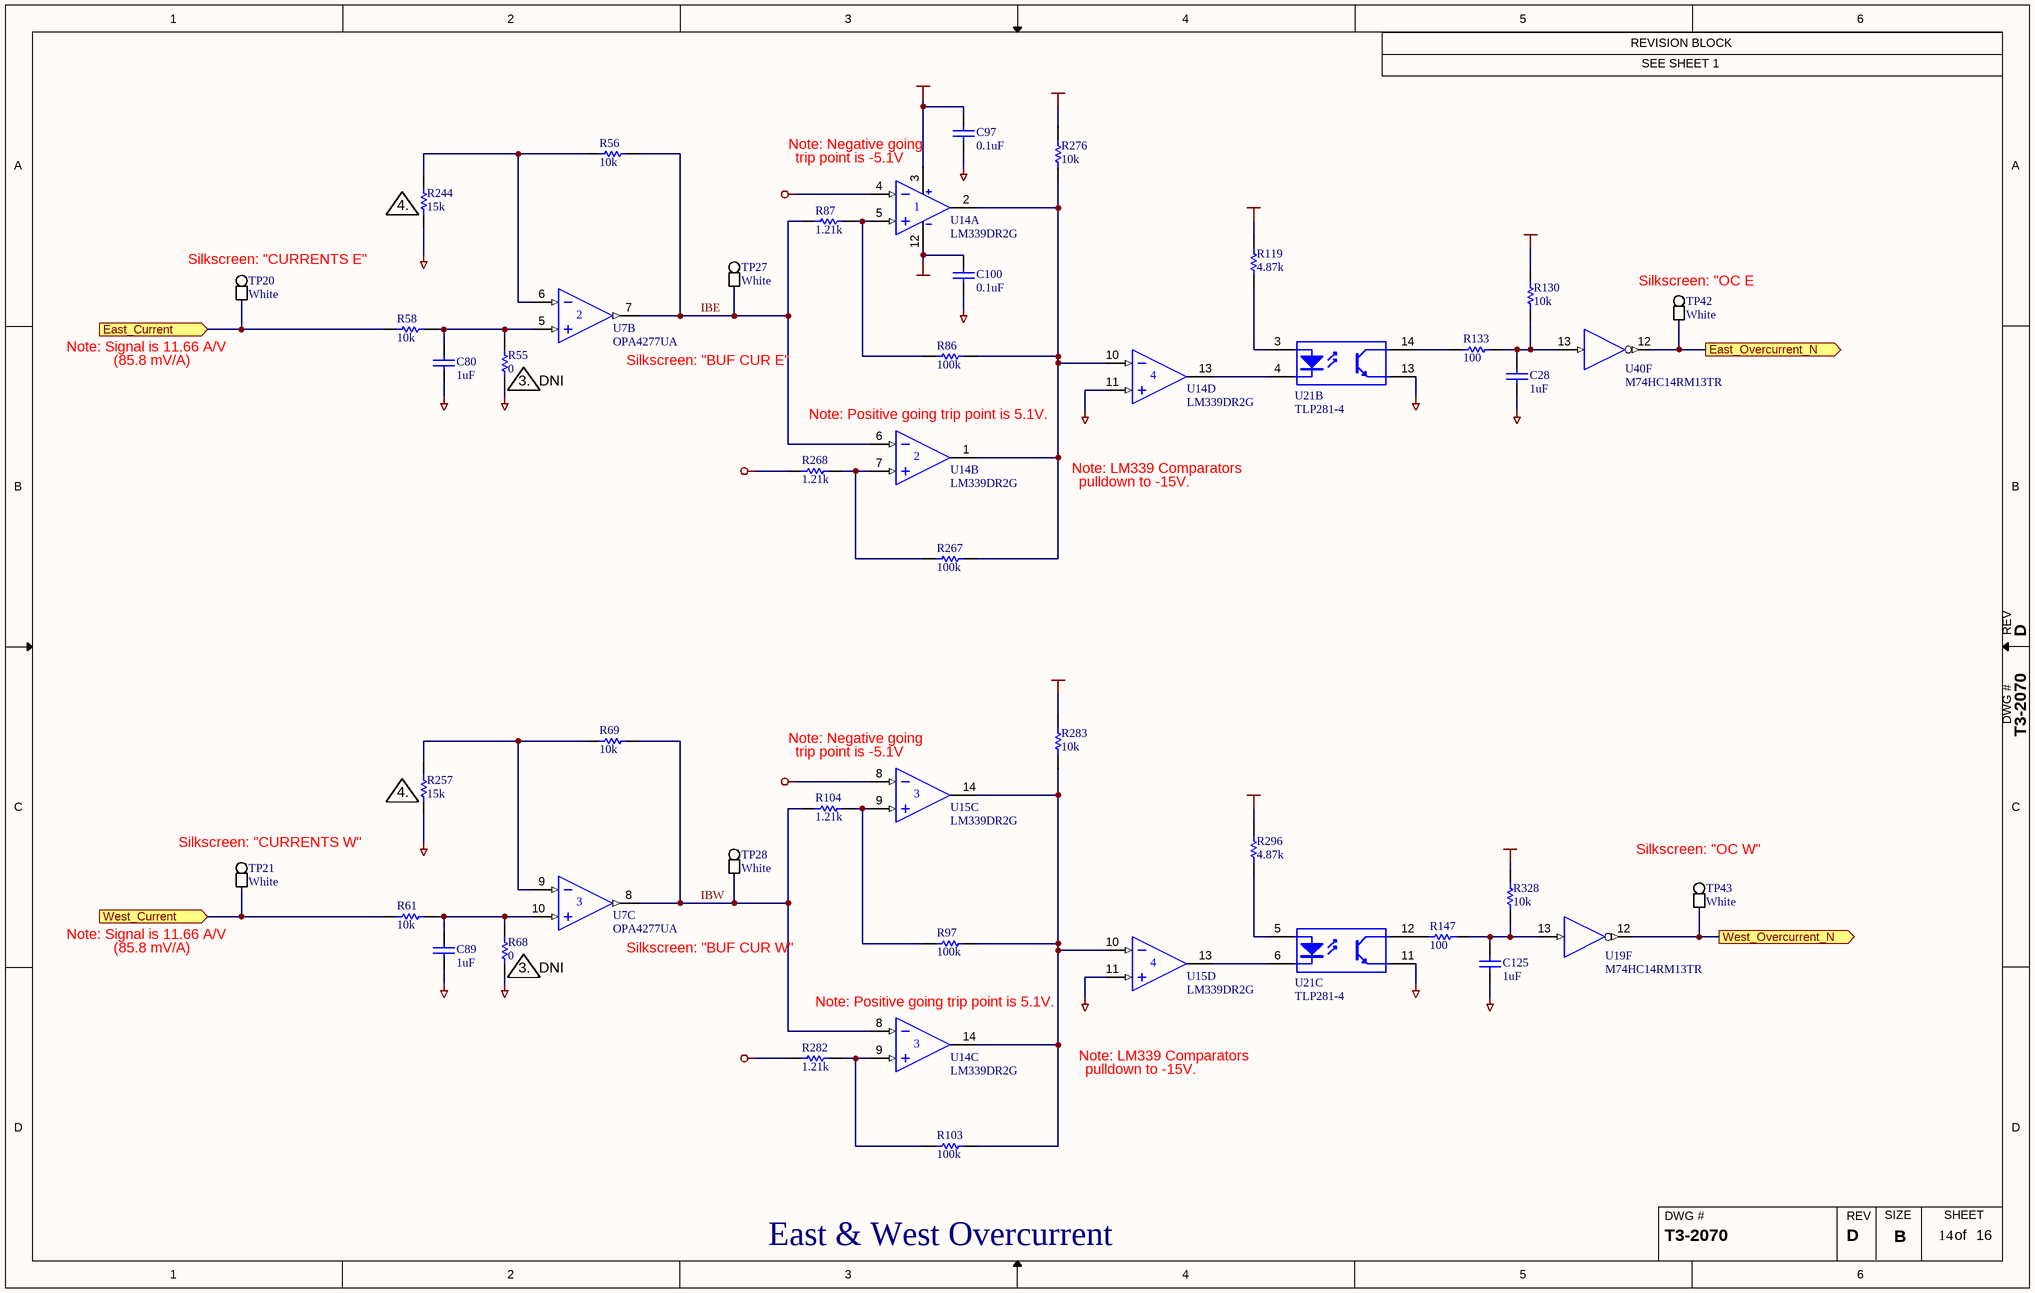
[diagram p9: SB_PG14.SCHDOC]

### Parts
(Parts that share a designator on the sheet are numbered #1, #2 ... from top to bottom, then left to right.)
C28  1uF  [1206]
C80  1uF  [1206]
C89  1uF  [1206]
C97  0.1uF  [1206]
C100  0.1uF  [1206]
C125  1uF  [1206]
Flag?#33  Flag#: 4.  (hidden comment: Flag)  (graphical)
Flag?#34  Flag#: 3.  Note: DNI  (graphical)
Flag?#35  Flag#: 4.  (hidden comment: Flag)  (graphical)
Flag?#36  Flag#: 3.  Note: DNI  (graphical)
R55  value 0  [1206]  (hidden comment: 0_jumper)  (no BOM)
R56  value 10k  [1206]  (hidden comment: 10000)
R58  value 10k  [1206]  (hidden comment: 10000)
R61  value 10k  [1206]  (hidden comment: 10000)
R68  value 0  [1206]  (hidden comment: 0_jumper)  (no BOM)
R69  value 10k  [1206]  (hidden comment: 10000)
R86  value 100k  [1206]  (hidden comment: 100000)
R87  value 1.21k  [1206]  (hidden comment: 1210)
R97  value 100k  [1206]  (hidden comment: 100000)
R103  value 100k  [1206]  (hidden comment: 100000)
R104  value 1.21k  [1206]  (hidden comment: 1210)
R119  value 4.87k  [1206]  (hidden comment: 4870)
R130  value 10k  [1206]  (hidden comment: 10000)
R133  100  [1206]
R147  100  [1206]
R244  value 15k  [1206]  (hidden comment: 15000)
R257  value 15k  [1206]  (hidden comment: 15000)
R267  value 100k  [1206]  (hidden comment: 100000)
R268  value 1.21k  [1206]  (hidden comment: 1210)
R276  value 10k  [1206]  (hidden comment: 10000)
R282  value 1.21k  [1206]  (hidden comment: 1210)
R283  value 10k  [1206]  (hidden comment: 10000)
R296  value 4.87k  [1206]  (hidden comment: 4870)
R328  value 10k  [1206]  (hidden comment: 10000)
TP20  value White  [TP_COMPACT]  (hidden comment: TP_5007)
TP21  value White  [TP_COMPACT]  (hidden comment: TP_5007)
TP27  value White  [TP_COMPACT]  (hidden comment: TP_5007)
TP28  value White  [TP_COMPACT]  (hidden comment: TP_5007)
TP42  value White  [TP_COMPACT]  (hidden comment: TP_5007)
TP43  value White  [TP_COMPACT]  (hidden comment: TP_5007)
U7  OPA4277UA  [SOIC_14_Narrow]  (parts B,C of 4)
U14  LM339DR2G  [SOIC_14_Narrow]  (parts A,B,C,D of 4)
U15  LM339DR2G  [SOIC_14_Narrow]  (parts C,D of 4)
U19  M74HC14RM13TR  [SOIC_14_Narrow]  (part F of 6)
U21  TLP281-4  [SOIC_16_C5.85]  (parts B,C of 4)
U40  M74HC14RM13TR  [SOIC_14_Narrow]  (part F of 6)

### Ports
East_Current (in), East_Overcurrent_N (out), West_Current (in), West_Overcurrent_N (out)

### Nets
+5_VREF: R268.1 R282.1
+5V_DIG: R130.2 R328.2
+15V: C97.2 R119.2 R276.2 R283.2 R296.2 U14.3(V+)
-5_VREF: U14.4(IN-) U15.8(IN-)
-15V: C100.2 U14.12(V-)
AGND: C80.1 C89.1 C97.1 C100.1 R55.1 R68.1 R244.1 R257.1 U14.11(IN+) U15.11(IN+)
DGND: C28.1 C125.1 U21.11(E) U21.13(E)
East Current: R58.1 TP20.1 ; port East_Current
East_Overcurrent_N: TP42.1 U40.12(~{OUT}) ; port East_Overcurrent_N
IBE: R56.2 R87.1 TP27.1 U7.7(OUT) U14.6(IN-)
IBW: R69.2 R104.1 TP28.1 U7.8(OUT) U14.8(IN-)
West Current: R61.1 TP21.1 ; port West_Current
West_Overcurrent_N: TP43.1 U19.12(~{OUT}) ; port West_Overcurrent_N
NetC28_2: C28.2 R130.1 R133.1 U40.13(IN)
NetC80_2: C80.2 R55.2 R58.2 U7.5(IN+)
NetC89_2: C89.2 R61.2 R68.2 U7.10(IN+)
NetC125_2: C125.2 R147.1 R328.1 U19.13(IN)
NetR56_1: R56.1 R244.2 U7.6(IN-)
NetR69_1: R69.1 R257.2 U7.9(IN-)
NetR86_1: R86.1 R87.2 U14.5(IN+)
NetR86_2: R86.2 R267.2 R276.1 U14.1(OUT) U14.2(OUT) U14.10(IN-)
NetR97_1: R97.1 R104.2 U15.9(IN+)
NetR97_2: R97.2 R103.2 R283.1 U14.14(OUT) U15.10(IN-) U15.14(OUT)
NetR103_1: R103.1 R282.2 U14.9(IN+)
NetR119_1: R119.1 U21.3(A)
NetR133_2: R133.2 U21.14(C)
NetR147_2: R147.2 U21.12(C)
NetR267_1: R267.1 R268.2 U14.7(IN+)
NetR296_1: R296.1 U21.5(A)
NetU14_13: U14.13(OUT) U21.4(K)
NetU15_13: U15.13(OUT) U21.6(K)

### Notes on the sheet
- Note: Negative going
- trip point is -5.1V
- (near TP20) Silkscreen: "CURRENTS E"
- (near TP42) Silkscreen: "OC E
- (near TP20) Note: Signal is 11.66 A/V
- (85.8 mV/A)
- (near U7) Silkscreen: "BUF CUR E"
- (near U14) Note: Positive going trip point is 5.1V.
- Note: LM339 Comparators
- pulldown to -15V.
- (near U15) Note: Negative going
- (near U15) trip point is -5.1V
- (near TP21) Silkscreen: "CURRENTS W"
- (near TP43) Silkscreen: "OC W"
- (near TP21) Note: Signal is 11.66 A/V
- (near U7) Silkscreen: "BUF CUR W"
- Note: Positive going trip point is 5.1V.
- East & West Overcurrent

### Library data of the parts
C28 C80 C89 C125 = 1uF: as C138 on sheet SB_PG6
C97 C100 = 0.1uF: as C33 on sheet SB_PG6
Flag?#34 Flag?#36 = Flag
R55 R68 = 0_jumper: as R161 on sheet SB_PG6
R56 R58 R61 R69 R130 R276 R283 R328 = 10000: as R181 on sheet SB_PG6
R86 R97 R103 R267 = 100000: as R169 on sheet SB_PG6
R87 R104 R268 R282 = 1210: as R84 on sheet SB_PG11
R119 R296 = 4870: as R17 on sheet SB_PG2
R133 R147 = 100: as R309 on sheet SB_PG11
R244 R257 = 15000: Thick Film Chip Resistor, 15k Ohm, 1% Tolerance, 1206 Size, 0.25 W; Part Number: ERJ-8ENF1502V; Manufacturer: Panasonic; Power Rating: 0.25W
TP20 TP21 TP27 TP28 TP42 TP43 = TP_5007: as TP19 on sheet SB_PG11
U7 = OPA4277UA: as U6 on sheet SB_PG11
U14 U15 = LM339DR2G: as U11 on sheet SB_PG11
U19 U40 = M74HC14RM13TR: as U28 on sheet SB_PG6
U21 = TLP281-4: Photocoupler; Manufacturer: Toshiba

## Sheet SB_PG15.SCHDOC: (Title)
size B; PageSetup: Record=PageOptions|CenterHorizontal=True|CenterVertical=True|PrintScale=1.09|XCorrection=1.00|YCorrection=1.00|PrintKind=0|BorderSize=5000000|LeftOffset=0|BottomOffset=0|Orientation=2|PaperLength=1000|PaperWidth=1000|Scale=100|PaperSource=7|PrintQuality=-4|MediaType=1|DitherType=10|PaperKind=11x17|PrintScaleMode=1; Engineer: (Engineer); Organization: Institute for Astronomy; Address1: 640 N. Aohoku Place; Address2: Hilo, HI 96720; DocumentNumber: T3-2070; Revision: D; SheetNumber: 15; SheetTotal: 16
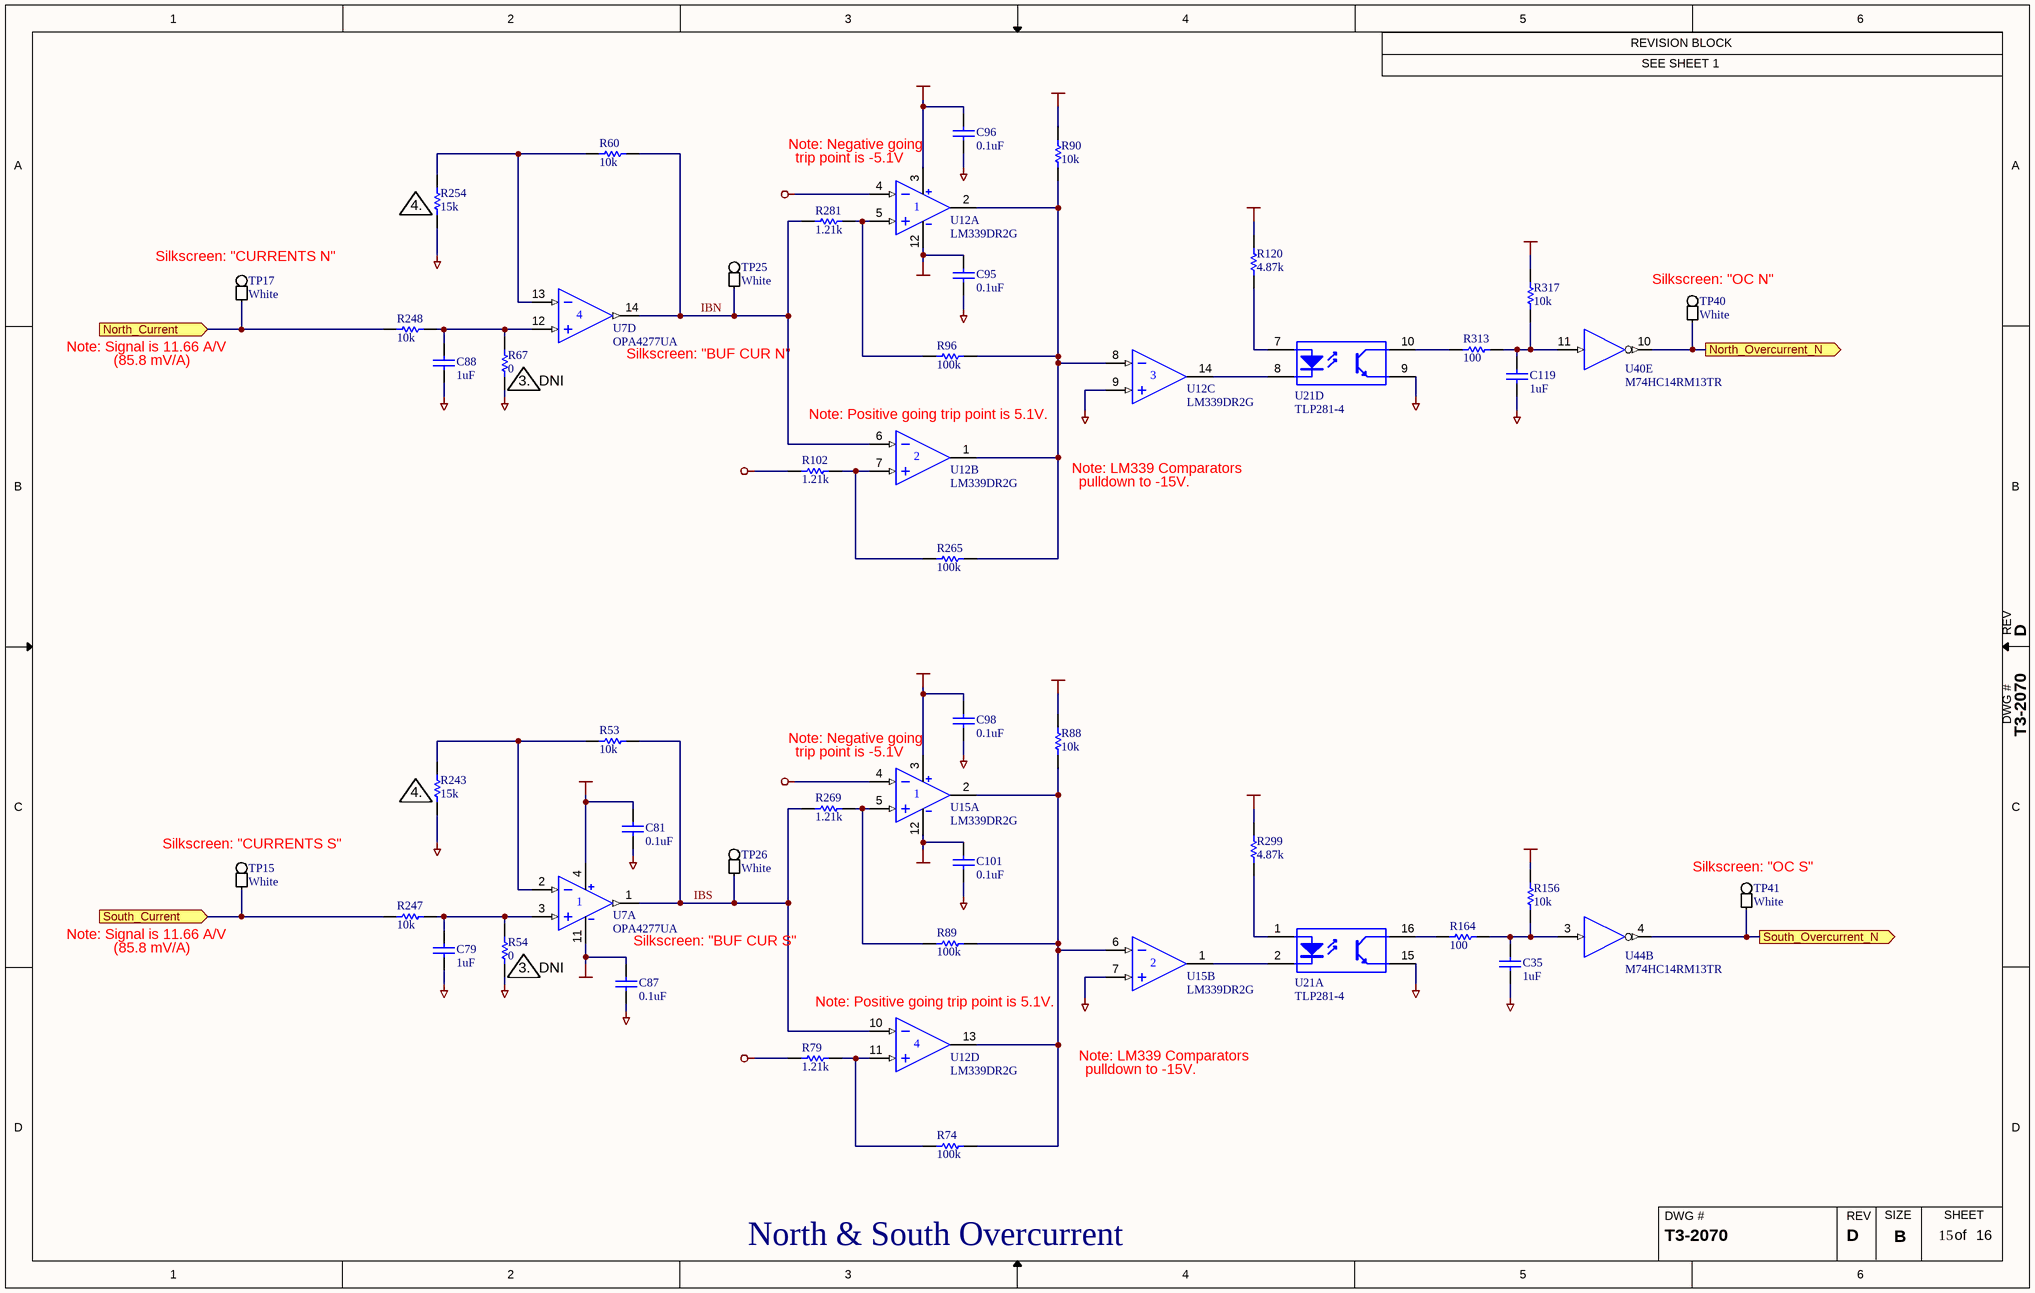
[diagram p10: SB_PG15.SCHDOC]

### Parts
(Parts that share a designator on the sheet are numbered #1, #2 ... from top to bottom, then left to right.)
C35  1uF  [1206]
C79  1uF  [1206]
C81  0.1uF  [1206]
C87  0.1uF  [1206]
C88  1uF  [1206]
C95  0.1uF  [1206]
C96  0.1uF  [1206]
C98  0.1uF  [1206]
C101  0.1uF  [1206]
C119  1uF  [1206]
Flag?#37  Flag#: 4.  (hidden comment: Flag)  (graphical)
Flag?#38  Flag#: 3.  Note: DNI  (graphical)
Flag?#39  Flag#: 4.  (hidden comment: Flag)  (graphical)
Flag?#40  Flag#: 3.  Note: DNI  (graphical)
R53  value 10k  [1206]  (hidden comment: 10000)
R54  value 0  [1206]  (hidden comment: 0_jumper)  (no BOM)
R60  value 10k  [1206]  (hidden comment: 10000)
R67  value 0  [1206]  (hidden comment: 0_jumper)  (no BOM)
R74  value 100k  [1206]  (hidden comment: 100000)
R79  value 1.21k  [1206]  (hidden comment: 1210)
R88  value 10k  [1206]  (hidden comment: 10000)
R89  value 100k  [1206]  (hidden comment: 100000)
R90  value 10k  [1206]  (hidden comment: 10000)
R96  value 100k  [1206]  (hidden comment: 100000)
R102  value 1.21k  [1206]  (hidden comment: 1210)
R120  value 4.87k  [1206]  (hidden comment: 4870)
R156  value 10k  [1206]  (hidden comment: 10000)
R164  100  [1206]
R243  value 15k  [1206]  (hidden comment: 15000)
R247  value 10k  [1206]  (hidden comment: 10000)
R248  value 10k  [1206]  (hidden comment: 10000)
R254  value 15k  [1206]  (hidden comment: 15000)
R265  value 100k  [1206]  (hidden comment: 100000)
R269  value 1.21k  [1206]  (hidden comment: 1210)
R281  value 1.21k  [1206]  (hidden comment: 1210)
R299  value 4.87k  [1206]  (hidden comment: 4870)
R313  100  [1206]
R317  value 10k  [1206]  (hidden comment: 10000)
TP15  value White  [TP_COMPACT]  (hidden comment: TP_5007)
TP17  value White  [TP_COMPACT]  (hidden comment: TP_5007)
TP25  value White  [TP_COMPACT]  (hidden comment: TP_5007)
TP26  value White  [TP_COMPACT]  (hidden comment: TP_5007)
TP40  value White  [TP_COMPACT]  (hidden comment: TP_5007)
TP41  value White  [TP_COMPACT]  (hidden comment: TP_5007)
U7  OPA4277UA  [SOIC_14_Narrow]  (parts A,D of 4)
U12  LM339DR2G  [SOIC_14_Narrow]  (parts A,B,C,D of 4)
U15  LM339DR2G  [SOIC_14_Narrow]  (parts A,B of 4)
U21  TLP281-4  [SOIC_16_C5.85]  (parts A,D of 4)
U40  M74HC14RM13TR  [SOIC_14_Narrow]  (part E of 6)
U44  M74HC14RM13TR  [SOIC_14_Narrow]  (part B of 6)

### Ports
North_Current (in), North_Overcurrent_N (out), South_Current (in), South_Overcurrent_N (out)

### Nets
+5_VREF: R79.1 R102.1
+5V_DIG: R156.2 R317.2
+15V: C81.2 C96.2 C98.2 R88.2 R90.2 R120.2 R299.2 U7.4(V+) U12.3(V+) U15.3(V+)
-5_VREF: U12.4(IN-) U15.4(IN-)
-15V: C87.2 C95.2 C101.2 U7.11(V-) U12.12(V-) U15.12(V-)
AGND: C79.1 C81.1 C87.1 C88.1 C95.1 C96.1 C98.1 C101.1 R54.1 R67.1 R243.1 R254.1 U12.9(IN+) U15.7(IN+)
DGND: C35.1 C119.1 U21.9(E) U21.15(E)
IBN: R60.2 R281.1 TP25.1 U7.14(OUT) U12.6(IN-)
IBS: R53.2 R269.1 TP26.1 U7.1(OUT) U12.10(IN-)
North Current: R248.1 TP17.1 ; port North_Current
North_Overcurrent_N: TP40.1 U40.10(~{OUT}) ; port North_Overcurrent_N
South Current: R247.1 TP15.1 ; port South_Current
South_Overcurrent_N: TP41.1 U44.4(~{OUT}) ; port South_Overcurrent_N
NetC35_2: C35.2 R156.1 R164.1 U44.3(IN)
NetC79_2: C79.2 R54.2 R247.2 U7.3(IN+)
NetC88_2: C88.2 R67.2 R248.2 U7.12(IN+)
NetC119_2: C119.2 R313.1 R317.1 U40.11(IN)
NetR53_1: R53.1 R243.2 U7.2(IN-)
NetR60_1: R60.1 R254.2 U7.13(IN-)
NetR74_1: R74.1 R79.2 U12.11(IN+)
NetR74_2: R74.2 R88.1 R89.2 U12.13(OUT) U15.2(OUT) U15.6(IN-)
NetR89_1: R89.1 R269.2 U15.5(IN+)
NetR90_1: R90.1 R96.2 R265.2 U12.1(OUT) U12.2(OUT) U12.8(IN-)
NetR96_1: R96.1 R281.2 U12.5(IN+)
NetR102_2: R102.2 R265.1 U12.7(IN+)
NetR120_1: R120.1 U21.7(A)
NetR164_2: R164.2 U21.16(C)
NetR299_1: R299.1 U21.1(A)
NetR313_2: R313.2 U21.10(C)
NetU12_14: U12.14(OUT) U21.8(K)
NetU15_1: U15.1(OUT) U21.2(K)

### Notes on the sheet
- Note: Negative going
- trip point is -5.1V
- (near TP17) Silkscreen: "CURRENTS N"
- (near TP40) Silkscreen: "OC N"
- (near TP17) Note: Signal is 11.66 A/V
- (85.8 mV/A)
- (near U7) Silkscreen: "BUF CUR N"
- (near U12) Note: Positive going trip point is 5.1V.
- Note: LM339 Comparators
- pulldown to -15V.
- (near U15) trip point is -5.1V
- (near TP15) Silkscreen: "CURRENTS S"
- (near TP41) Silkscreen: "OC S"
- (near TP15) Note: Signal is 11.66 A/V
- Silkscreen: "BUF CUR S"
- Note: Positive going trip point is 5.1V.
- North & South Overcurrent

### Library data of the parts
C35 C79 C88 C119 = 1uF: as C138 on sheet SB_PG6
C81 C87 C95 C96 C98 C101 = 0.1uF: as C33 on sheet SB_PG6
Flag?#38 Flag?#40 = Flag
R53 R60 R88 R90 R156 R247 R248 R317 = 10000: as R181 on sheet SB_PG6
R54 R67 = 0_jumper: as R161 on sheet SB_PG6
R74 R89 R96 R265 = 100000: as R169 on sheet SB_PG6
R79 R102 R269 R281 = 1210: as R84 on sheet SB_PG11
R120 R299 = 4870: as R17 on sheet SB_PG2
R164 R313 = 100: as R309 on sheet SB_PG11
R243 R254 = 15000: as R244 on sheet SB_PG14
TP15 TP17 TP25 TP26 TP40 TP41 = TP_5007: as TP19 on sheet SB_PG11
U7 = OPA4277UA: as U6 on sheet SB_PG11
U12 U15 = LM339DR2G: as U11 on sheet SB_PG11
U21 = TLP281-4: Photocoupler; Manufacturer: Toshiba
U40 U44 = M74HC14RM13TR: as U28 on sheet SB_PG6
